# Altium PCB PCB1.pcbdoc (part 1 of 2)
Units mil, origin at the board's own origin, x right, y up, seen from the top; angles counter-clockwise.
Board outline 1377.9 x 2559.1 mil, 4 copper layers (Top Layer, Inner1, Inner2, Bottom Layer), stack 62.5 mil thick; 243 components, 192 nets, 1028 pads, 96 vias.
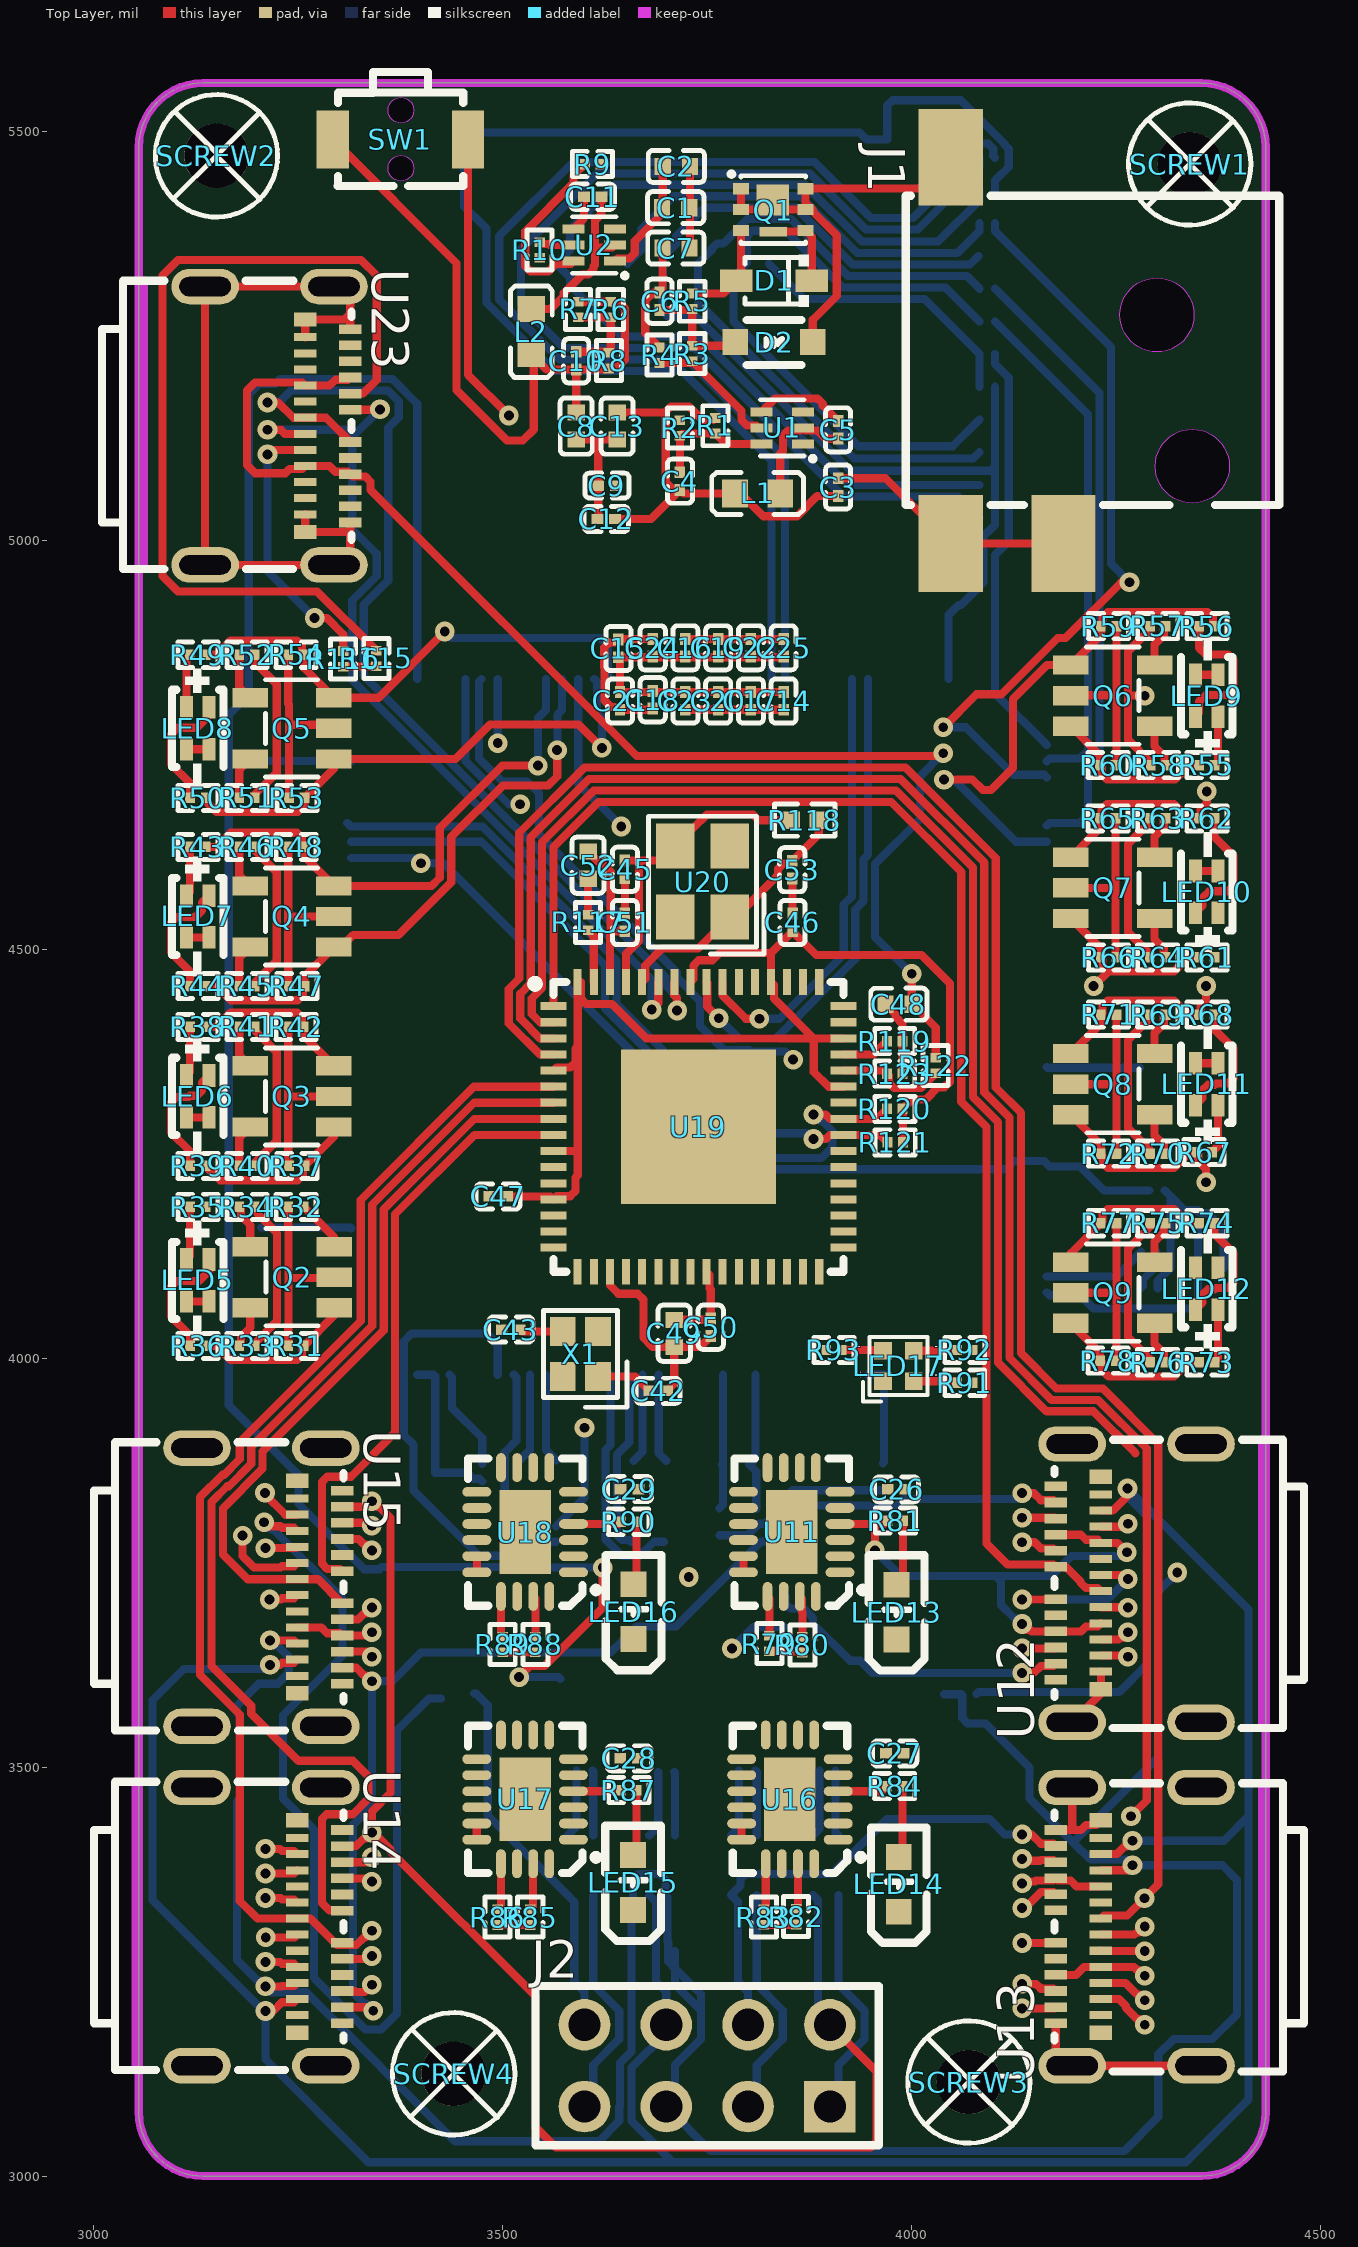
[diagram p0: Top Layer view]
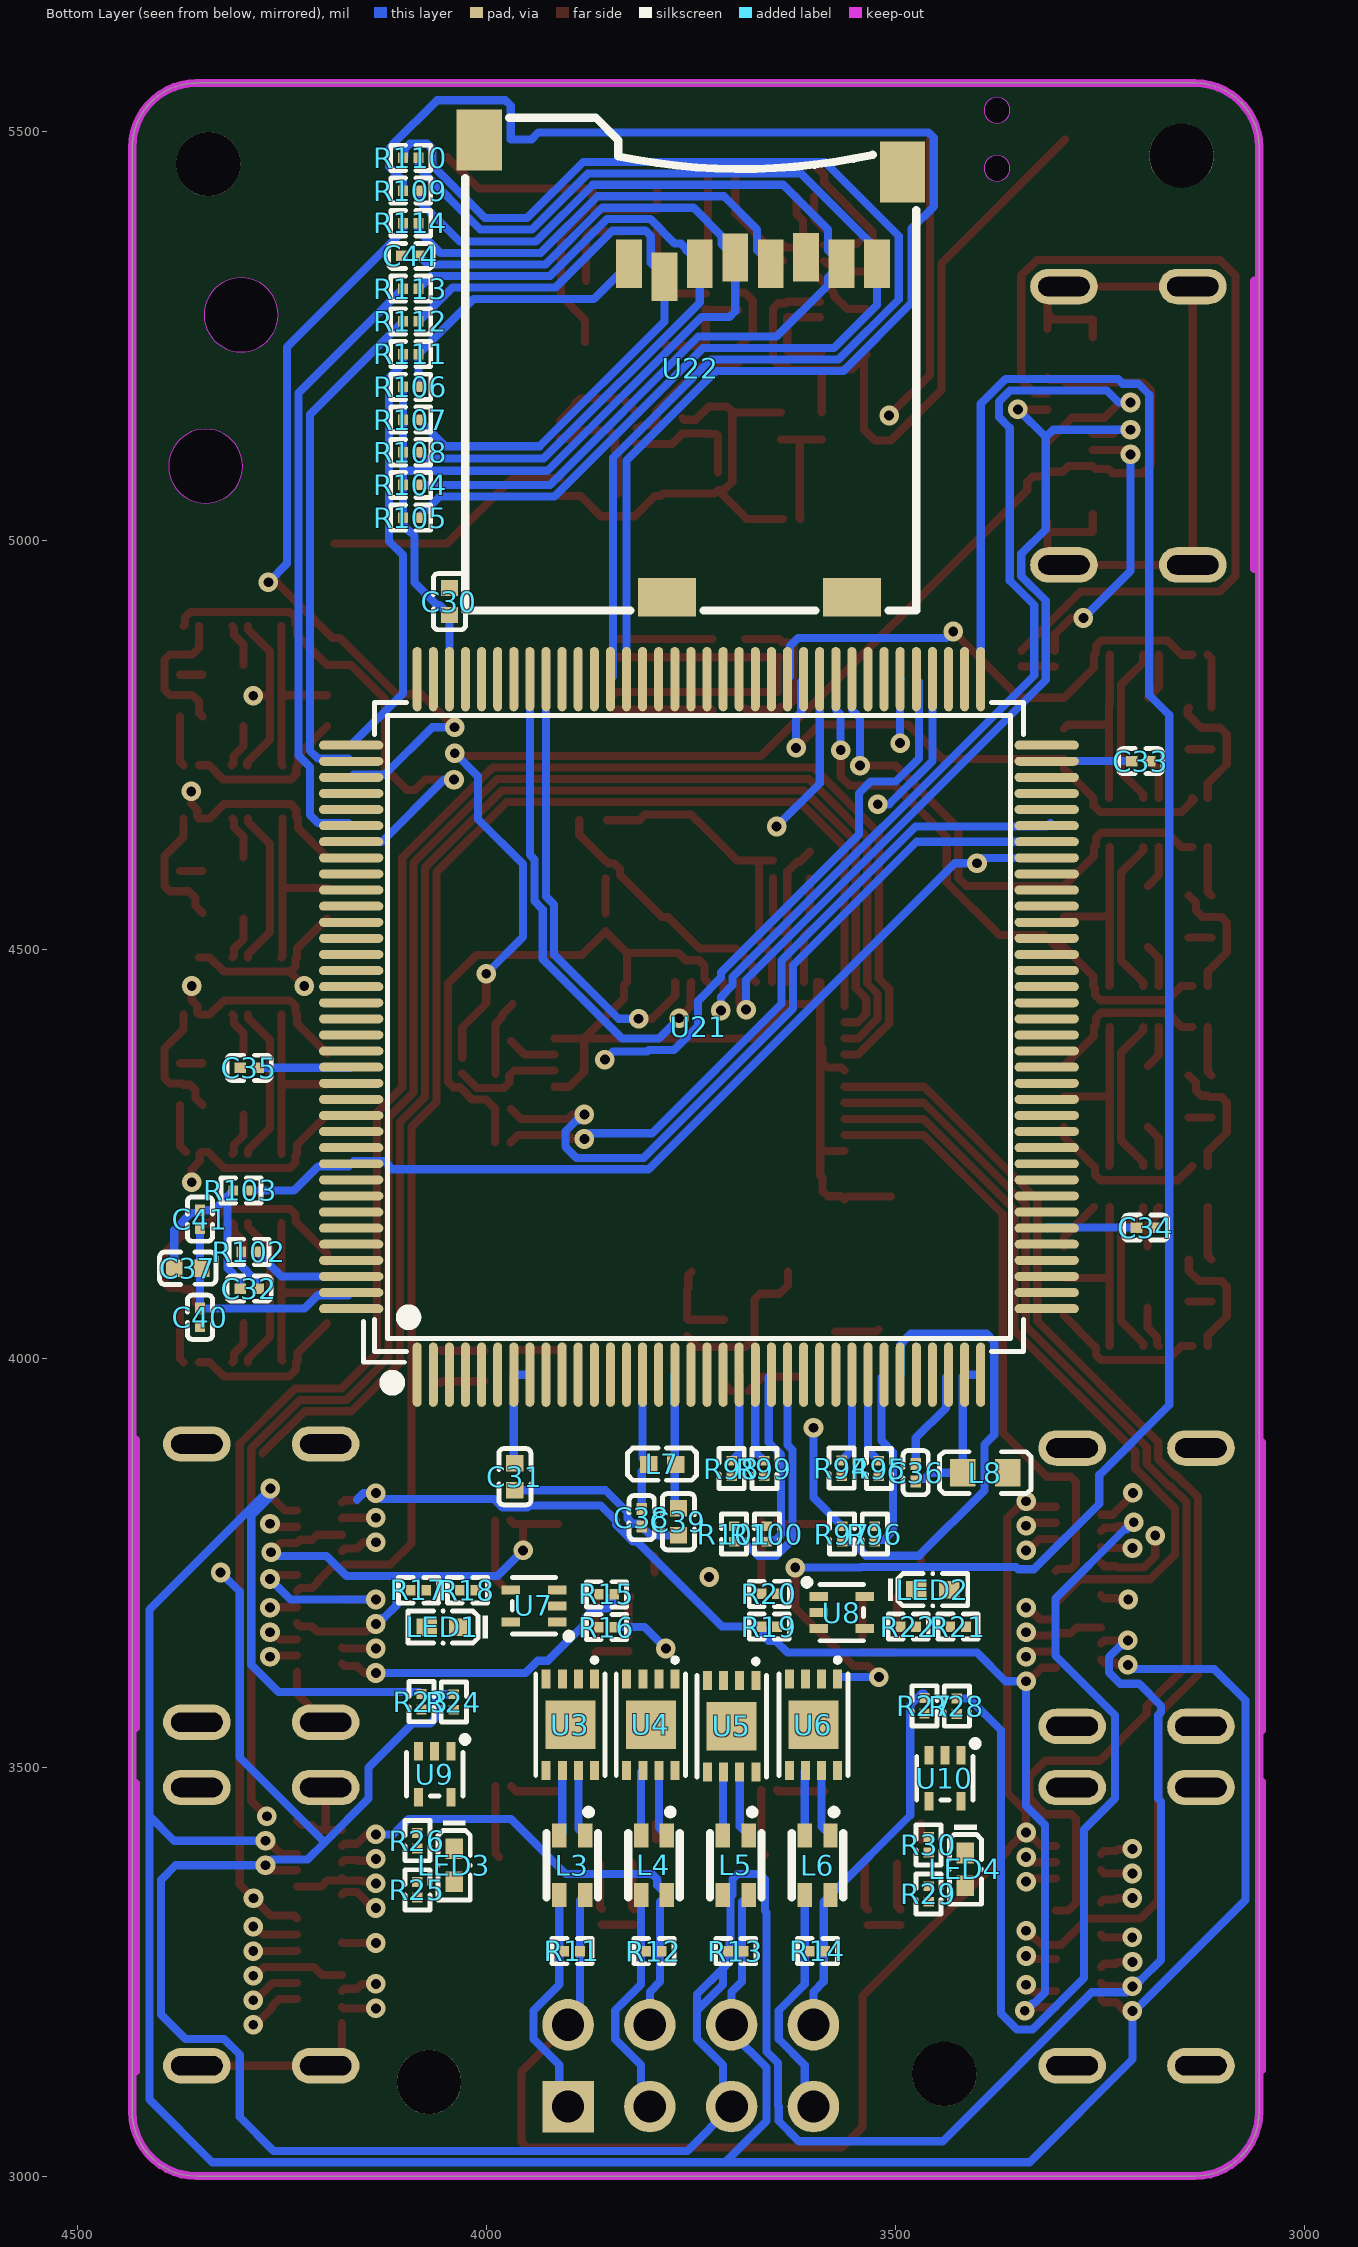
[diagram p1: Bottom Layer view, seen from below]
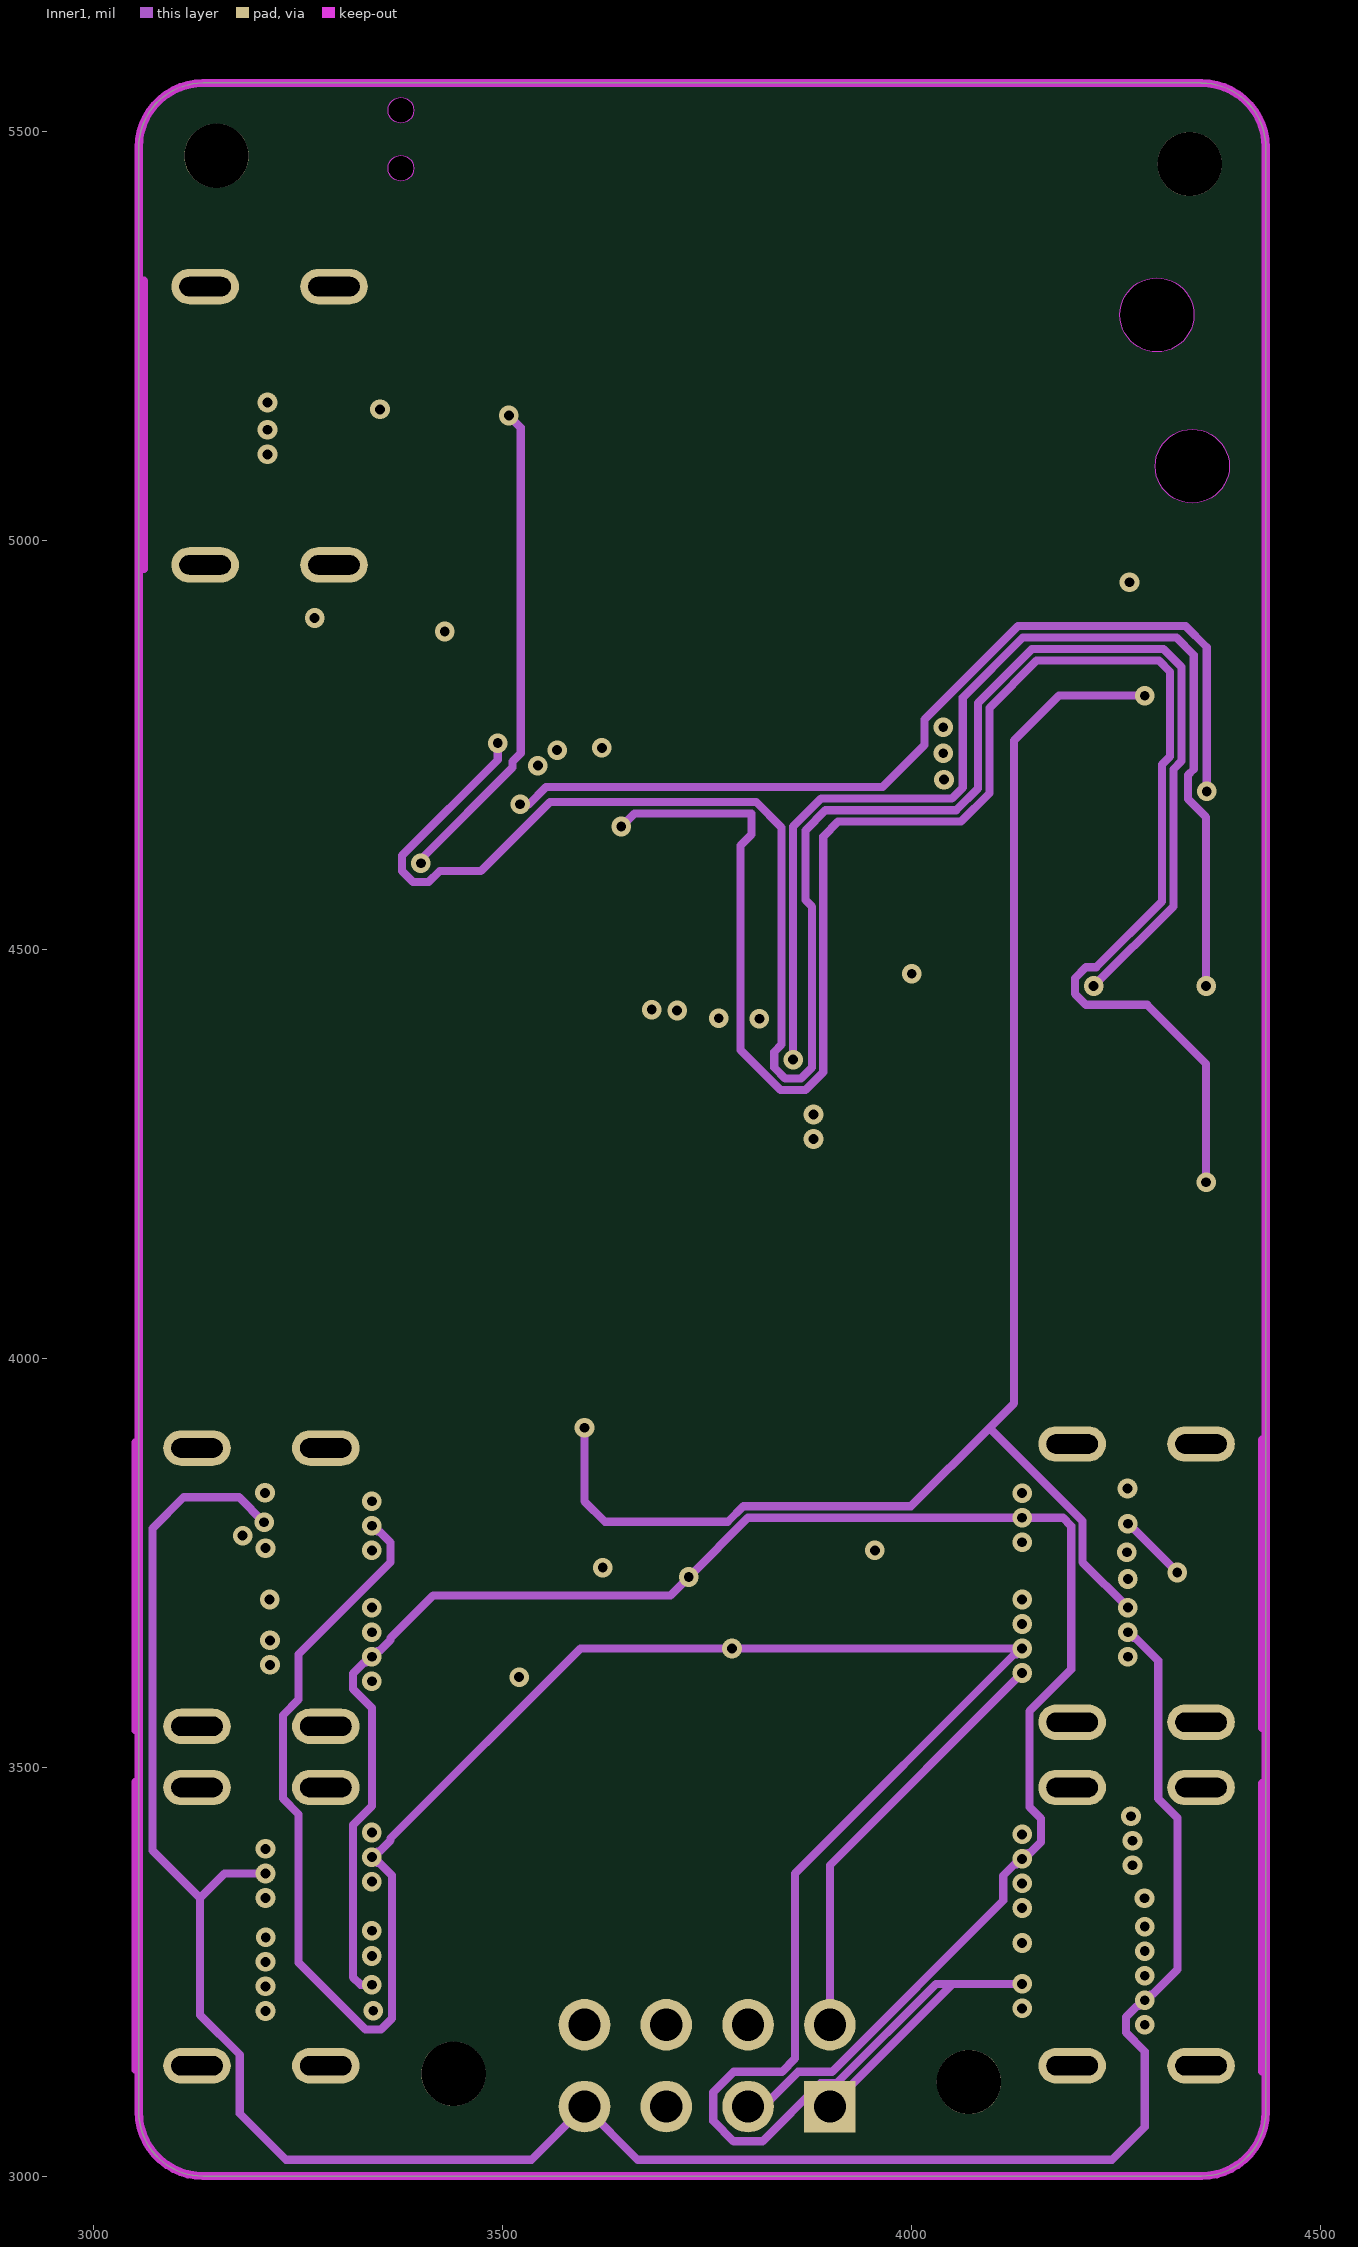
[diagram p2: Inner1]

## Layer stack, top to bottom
Top Layer: signal copper 1.4
Dielectric1: surface 8.3, 7628 RC49% 8.6mil, Dk 0
Inner1: signal copper 0.6
Dielectric2: surface 41.9, 1.1mm H/HOZ Copper, Dk 0
Inner2: signal copper 0.6
Dielectric3: surface 8.3, 7628 RC49% 8.6mil, Dk 0
Bottom Layer: signal copper 1.4

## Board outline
3133.5,5559.1 ccw(c3133.5,5480.3) 3054.8,5480.3 3054.8,3078.7 ccw(c3133.5,3078.7) 3133.5,3000 4354,3000 ccw(c4354,3078.7) 4432.7,3078.7 4432.7,5480.3 ccw(c4354,5480.3) 4354,5559.1 3133.5,5559.1

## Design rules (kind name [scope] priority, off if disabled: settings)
BoardOutlineClearance copperThickness1oz [All] p0: genericclearance=10 ignorepadtopadclearanceinfootprint=FALSE except(0: Arc-SplitContinuation Track-SplitContinuation SMDPad-SplitContinuation THPad-SplitContinuation Via-SplitContinuation Fill-SplitContinuation Poly-SplitContinuation Region-SplitContinuation Text-SplitContinuation)
BoardOutlineClearance copperThickness2oz [All] p0: genericclearance=10 ignorepadtopadclearanceinfootprint=FALSE except(0: Arc-SplitContinuation Track-SplitContinuation SMDPad-SplitContinuation THPad-SplitContinuation Via-SplitContinuation Fill-SplitContinuation Poly-SplitContinuation Region-SplitContinuation Text-SplitContinuation)
BoardOutlineClearance Plane_innerPlane [All] p0: genericclearance=10 ignorepadtopadclearanceinfootprint=FALSE except(0: Arc-SplitContinuation Track-SplitContinuation SMDPad-SplitContinuation THPad-SplitContinuation Via-SplitContinuation Fill-SplitContinuation Poly-SplitContinuation Region-SplitContinuation Text-SplitContinuation)
BoardOutlineClearance Copper_copperRegion [All] p0: genericclearance=10 ignorepadtopadclearanceinfootprint=FALSE except(0: Arc-SplitContinuation Track-SplitContinuation SMDPad-SplitContinuation THPad-SplitContinuation Via-SplitContinuation Fill-SplitContinuation Poly-SplitContinuation Region-SplitContinuation Text-SplitContinuation)
BoardOutlineClearance otherClearance [All] p0: genericclearance=10 ignorepadtopadclearanceinfootprint=FALSE except(0: Arc-SplitContinuation Track-SplitContinuation SMDPad-SplitContinuation THPad-SplitContinuation Via-SplitContinuation Fill-SplitContinuation Poly-SplitContinuation Region-SplitContinuation Text-SplitContinuation)
Clearance copperThickness1oz [All] p1: gap=7 ignorepadtopadclearanceinfootprint=FALSE
Clearance copperThickness2oz [All] p1: gap=7 ignorepadtopadclearanceinfootprint=FALSE
Clearance Plane_innerPlane [All] p1: gap=7 ignorepadtopadclearanceinfootprint=FALSE
Clearance Copper_copperRegion [All] p1: gap=7 ignorepadtopadclearanceinfootprint=FALSE
Clearance otherClearance [All] p1: gap=7 ignorepadtopadclearanceinfootprint=FALSE
DiffPairsRouting differentialPair [All] p1: maxuncoupledlength=10 minlimit=6 maxlimit=Infinity mostfreqgap=6 toplayer_minwidth=5 toplayer_prefwidth=10 toplayer_maxwidth=100 bottomlayer_minwidth=5 bottomlayer_prefwidth=10 bottomlayer_maxwidth=100 midlayer1_minwidth=5 midlayer1_prefwidth=10 midlayer1_maxwidth=100 midlayer2_minwidth=5 midlayer2_prefwidth=10 midlayer2_maxwidth=100
PasteMaskExpansion pasteMaskExpansion [All] p1: expansion=0
PlaneConnect innerPlane [All] p1: planeconnectstyle=Relief reliefexpansion=20 reliefentries=4 reliefconductorwidth=10 reliefairgap=10
PolygonConnect copperRegion [All] p1: connectstyle=Relief reliefentries=4 reliefconductorwidth=10 polygonreliefangle="90 Angle" airgapwidth=10
RoutingVias viaSize [All] p1: viastyle="Through Hole" holewidth=12.0078 minholewidth=11.811 maxholewidth=248.0314 width=12.0078 minwidth=11.811 maxwidth=248.0314
SolderMaskExpansion solderMaskExpansion [IsVia] p1: useseparateexpansions=TRUE expansion=-1000 expansionbottom=-1000
SolderMaskExpansion solderMaskExpansion [All] p2: useseparateexpansions=TRUE expansion=2 expansionbottom=2
Width copperThickness1oz [All] p1: maxlimit=100 minlimit=5 preferedwidth=10
Width copperThickness2oz [All] p1: maxlimit=100 minlimit=8 preferedwidth=10

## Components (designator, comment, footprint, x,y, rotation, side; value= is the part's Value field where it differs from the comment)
C1 "10uF" C0402#1 3711.3,5406.7 r180 top
C2 "10uF" C0402#1 3712.1,5457 r180 top
C3 "100nF" C0201 3909.8,5065 r90 top
C4 "100nF" C0201 3716.5,5072.3 r270 top
C5 "100nF" C0201 3909.8,5135 r270 top
C6 "100nF" C0201 3691.5,5292.3 r270 top
C7 "10uF" C0402#2 3711.5,5357.3 r180 top
C8 "10uF" C0402#3 3589.6,5139.6 r90 top
C9 "100nF" C0201 3627.3,5066.8 r180 top
C10 "100nF" C0201 3589.6,5219.6 r270 top
C11 "100nF" C0201 3609.8,5420 r0 top
C12 "100nF" C0201 3626.5,5026 r180 top
C13 "10uF" C0402#3 3639.6,5139.6 r90 top
C14 "100nF" C0201 3843.2,4803.5 r270 top
C15 "100nF" C0201 3641.3,4867.7 r90 top
C16 "100nF" C0201 3723.2,4868.5 r90 top
C17 "100nF" C0201 3803.2,4803.5 r270 top
C18 "100nF" C0201 3683.2,4805.1 r270 top
C19 "100nF" C0201 3763.2,4868.5 r90 top
C20 "100nF" C0201 3763.2,4803.5 r270 top
C21 "100nF" C0201 3643.2,4803.5 r270 top
C22 "100nF" C0201 3803.2,4868.5 r90 top
C23 "100nF" C0201 3723.2,4803.5 r270 top
C24 "100nF" C0201 3683.2,4868.5 r90 top
C25 "100nF" C0201 3843.2,4868.5 r90 top
C26 "10uF" C0201 3981.3,3839.5 r180 top
C27 "10uF" C0201 3979.1,3516.7 r0 top
C28 "10uF" C0201 3654.3,3510.8 r0 top
C29 "10uF" C0201 3654.8,3840 r0 top
C30 "10uF" C0402#2 4044.8,4925 r270 bottom
C31 "10uF" C0402#2 3964.8,3855 r90 bottom
C32 "100nF" C0201 4289.8,4085 r180 bottom
C33 "100nF" C0201 3199.8,4730 r0 bottom
C34 "100nF" C0201 3193.8,4159.6 r0 bottom
C35 "100nF" C0201 4289.8,4355 r180 bottom
C36 "100nF" C0201 3474.8,3860 r270 bottom
C37 "10uF" C0402#1 4364.8,4110 r180 bottom
C38 "220pF" C0201 3809.8,3805 r270 bottom
C39 "10uF" C0402#2 3764.8,3800 r90 bottom
C40 "100nF" C0201 4349.8,4050 r90 bottom
C41 "100nF" C0201 4349.8,4170 r270 bottom
C42 "12pF" C0201 3689.8,3960 r0 top
C43 "12pF" C0201 3509.8,4035 r0 top
C44 "10uF" C0201 4092.2,5347.6 r180 bottom
C45 "12pF" C0201 3649.2,4597.7 r270 top
C46 "100nF" C0201 3854.2,4532.7 r270 top
C47 "100nF" C0201 3494.2,4197.7 r0 top
C48 "10uF" C0402#3 3984.2,4432.7 r0 top
C49 "10uF" C0402#3 3709.5,4030.4 r90 top
C50 "100nF" C0201 3754.2,4037.7 r90 top
C51 "100nF" C0201 3649.2,4532.7 r270 top
C52 "10uF" C0402#1 3604.2,4602.7 r90 top
C53 "12pF" C0201 3853.8,4597.3 r270 top
D1 "B140WS-7" SOD-323_L1.8-W1.3-LS2.5-RD 3831.5,5317.3 r180 top
D2 "SOD-323" SOD-323_L1.7-W1.3-LS2.5-BI 3831.5,5242.3 r180 top
J1 "DC-044D-2.5A-2.0-SMT" DC-IN-SMD_DC-044D-2.5A-2.0-SMT 4116.5,5232.3 r270 top
J2 "SSQ-104-04-T-D" HDR-TH_8P-P2.54_SSW-104-23-F-D 3749.8,3135 r0 top
L1 "3.3uH" L0603#1 3811.5,5057.3 r180 top
L2 "3.3uH" L0603#1 3534.8,5255 r270 top
L3 "ACM2012-900-2P-T001" FILTER-SMD_4P-L2.0-W1.2-TL_ACM2012E 3894.8,3380 r270 bottom
L4 "ACM2012-900-2P-T001" FILTER-SMD_4P-L2.0-W1.2-TL_ACM2012E 3794.8,3380 r270 bottom
L5 "ACM2012-900-2P-T001" FILTER-SMD_4P-L2.0-W1.2-TL_ACM2012E 3694.8,3380 r270 bottom
L6 "ACM2012-900-2P-T001" FILTER-SMD_4P-L2.0-W1.2-TL_ACM2012E 3594.8,3380 r270 bottom
L7 "2.2uH" L0402 3784.8,3870 r0 bottom
L8 "3.3uH" L0603#2 3389.8,3860 r0 bottom
LED1 "APHHS1005LSECK/J3-PF" LED0402-RD_RED#1 4052.8,3671.2 r0 bottom
LED2 "APHHS1005LSECK/J3-PF" LED0402-RD_RED#2 3453.9,3716.9 r180 bottom
LED3 "APHHS1005LSECK/J3-PF" LED0402-RD_RED#1 4039,3380 r270 bottom
LED4 "APHHS1005LSECK/J3-PF" LED0402-RD_RED#1 3414,3375 r270 bottom
LED5 "HSMF-C163" LED-SMD_L1.6-W0.8_HSMF-C163 3127.1,4095 r270 top
LED6 "HSMF-C163" LED-SMD_L1.6-W0.8_HSMF-C163 3127.1,4320 r270 top
LED7 "HSMF-C163" LED-SMD_L1.6-W0.8_HSMF-C163 3127.1,4540 r270 top
LED8 "HSMF-C163" LED-SMD_L1.6-W0.8_HSMF-C163 3127.1,4770 r270 top
LED9 "HSMF-C163" LED-SMD_L1.6-W0.8_HSMF-C163 4360.6,4810 r90 top
LED10 "HSMF-C163" LED-SMD_L1.6-W0.8_HSMF-C163 4360.6,4570 r90 top
LED11 "HSMF-C163" LED-SMD_L1.6-W0.8_HSMF-C163 4360.6,4335 r90 top
LED12 "HSMF-C163" LED-SMD_L1.6-W0.8_HSMF-C163 4360.6,4085 r90 top
LED13 "SLED-0603-H0_8MM" LED0603-R-RD_RED 3981.3,3689.5 r90 top
LED14 "SLED-0603-H0_8MM" LED0603-R-RD_RED 3984.1,3356.7 r90 top
LED15 "SLED-0603-H0_8MM" LED0603-R-RD_RED 3659.2,3358.9 r90 top
LED16 "SLED-0603-H0_8MM" LED0603-R-RD_RED 3659.8,3690 r90 top
LED17 "TZ1615RGB3U-Common Yang" LED-SMD_TZ1615RGB3U-COMMON-YANG 3983.6,3990.4 r0 top
Q1 "AON2403" DFN-6_L2.0-W2.0-P0.65-BL-EP-1 3830.6,5403.7 r270 top
Q2 "QS5K2TR" SOT-23-5_L2.9-W1.6-P0.95-LS2.8-TL 3242.4,4099 r180 top
Q3 "QS5K2TR" SOT-23-5_L2.9-W1.6-P0.95-LS2.8-TL 3242.1,4320 r180 top
Q4 "QS5K2TR" SOT-23-5_L2.9-W1.6-P0.95-LS2.8-TL 3242.1,4540 r180 top
Q5 "QS5K2TR" SOT-23-5_L2.9-W1.6-P0.95-LS2.8-TL 3242.1,4770 r180 top
Q6 "QS5K2TR" SOT-23-5_L2.9-W1.6-P0.95-LS2.8-TL 4245.6,4810 r0 top
Q7 "QS5K2TR" SOT-23-5_L2.9-W1.6-P0.95-LS2.8-TL 4245.6,4575 r0 top
Q8 "QS5K2TR" SOT-23-5_L2.9-W1.6-P0.95-LS2.8-TL 4245.6,4335 r0 top
Q9 "QS5K2TR" SOT-23-5_L2.9-W1.6-P0.95-LS2.8-TL 4245.6,4080 r0 top
R1 "52.3kΩ" R0201#1 3759.8,5140 r90 top
R2 "10kΩ" R0201#1 3716.5,5137.3 r90 top
R3 "10kΩ" R0201#2 3731.5,5228.2 r90 top
R4 "10kΩ" R0201#1 3691.5,5226.3 r270 top
R5 "1kΩ" R0201#1 3731.5,5292.3 r270 top
R6 "100kΩ" R0201#1 3631.9,5282.2 r90 top
R7 "100kΩ" R0201#1 3591.9,5282.2 r90 top
R8 "100kΩ" R0201#1 3629.6,5219.6 r270 top
R9 "10kΩ" R0201#1 3609.8,5460 r180 top
R10 "10kΩ" R0201#1 3544.8,5355 r270 top
R11 "62Ω" R0201#1 3894.8,3275 r180 bottom
R12 "62Ω" R0201#1 3794.8,3275 r180 bottom
R13 "62Ω" R0201#1 3694.8,3275 r180 bottom
R14 "62Ω" R0201#1 3594.8,3275 r180 bottom
R15 "10kΩ" R0201#1 3852.8,3711.2 r0 bottom
R16 "10kΩ" R0201#1 3852.8,3671.2 r0 bottom
R17 "100kΩ" R0201#1 4082.8,3716.2 r0 bottom
R18 "2.7kΩ" R0201#1 4022.8,3716.2 r0 bottom
R19 "10kΩ" R0201#2 3653.9,3671.9 r180 bottom
R20 "10kΩ" R0201#2 3653.9,3711.9 r180 bottom
R21 "100kΩ" R0201#1 3422.9,3671.9 r180 bottom
R22 "2.7kΩ" R0201#2 3483.9,3671.9 r180 bottom
R23 "10kΩ" R0201#1 4079,3580 r270 bottom
R24 "10kΩ" R0201#1 4039.5,3579.5 r270 bottom
R25 "100kΩ" R0201#1 4084,3350 r270 bottom
R26 "2.7kΩ" R0201#1 4084,3410 r270 bottom
R27 "10kΩ" R0201#1 3464,3575 r270 bottom
R28 "10kΩ" R0201#1 3424.5,3574.5 r270 bottom
R29 "100kΩ" R0201#1 3459,3345 r270 bottom
R30 "2.7kΩ" R0201#1 3459,3405 r270 bottom
R31 "10kΩ" R0201#1 3247.1,4015 r0 top
R32 "10kΩ" R0201#1 3247.1,4185 r0 top
R33 "1kΩ" R0201#1 3187.1,4015 r0 top
R34 "100Ω" R0201#1 3187.1,4185 r0 top
R35 "100Ω" R0201#1 3127.1,4185 r0 top
R36 "100Ω" R0201#1 3127.1,4015 r0 top
R37 "10kΩ" R0201#1 3248.1,4235 r0 top
R38 "100Ω" R0201#1 3127.1,4405 r0 top
R39 "100Ω" R0201#1 3127.1,4235 r0 top
R40 "1kΩ" R0201#1 3187.1,4235 r0 top
R41 "100Ω" R0201#1 3187.1,4405 r0 top
R42 "10kΩ" R0201#1 3247.1,4405 r0 top
R43 "100Ω" R0201#1 3127.1,4625 r0 top
R44 "100Ω" R0201#1 3127.1,4455 r0 top
R45 "1kΩ" R0201#1 3187.1,4455 r0 top
R46 "100Ω" R0201#1 3187.1,4625 r0 top
R47 "10kΩ" R0201#1 3248.1,4455 r0 top
R48 "10kΩ" R0201#1 3247.1,4625 r0 top
R49 "100Ω" R0201#1 3127.1,4860 r0 top
R50 "100Ω" R0201#1 3127.1,4685 r0 top
R51 "1kΩ" R0201#1 3187.1,4685 r0 top
R52 "100Ω" R0201#1 3187.1,4860 r0 top
R53 "10kΩ" R0201#1 3248.1,4685 r0 top
R54 "10kΩ" R0201#1 3247.1,4860 r0 top
R55 "100Ω" R0201#1 4360.6,4725 r180 top
R56 "100Ω" R0201#1 4360.6,4895 r0 top
R57 "1kΩ" R0201#1 4300.6,4895 r180 top
R58 "100Ω" R0201#1 4301.6,4725 r180 top
R59 "10kΩ" R0201#1 4240.6,4895 r180 top
R60 "10kΩ" R0201#1 4239.6,4725 r180 top
R61 "100Ω" R0201#1 4360.6,4490 r180 top
R62 "100Ω" R0201#1 4360.6,4660 r180 top
R63 "1kΩ" R0201#1 4300.6,4660 r180 top
R64 "100Ω" R0201#1 4300.6,4490 r180 top
R65 "10kΩ" R0201#1 4239.6,4660 r180 top
R66 "10kΩ" R0201#1 4240.6,4490 r180 top
R67 "100Ω" R0201#1 4357.5,4252 r180 top
R68 "100Ω" R0201#1 4360.6,4420 r180 top
R69 "1kΩ" R0201#1 4300.6,4420 r180 top
R70 "100Ω" R0201#1 4300.6,4250 r180 top
R71 "10kΩ" R0201#1 4240.6,4420 r180 top
R72 "10kΩ" R0201#1 4240.6,4250 r180 top
R73 "100Ω" R0201#1 4360.6,3995 r180 top
R74 "100Ω" R0201#1 4360.6,4165 r180 top
R75 "1kΩ" R0201#1 4300.6,4165 r180 top
R76 "100Ω" R0201#1 4300.6,3995 r180 top
R77 "10kΩ" R0201#1 4240.6,4165 r180 top
R78 "10kΩ" R0201#1 4239.7,3997 r180 top
R79 "28kΩ" R0201#1 3825.8,3651.1 r270 top
R80 "33kΩ" R0201#1 3866.3,3649.5 r270 top
R81 "3.3kΩ" R0201#1 3979.8,3801.4 r180 top
R82 "33kΩ" R0201#2 3858.6,3317.3 r270 top
R83 "28kΩ" R0201#1 3819.1,3316.7 r270 top
R84 "3.3kΩ" R0201#1 3979.1,3476.7 r180 top
R85 "33kΩ" R0201#2 3533.5,3316.6 r270 top
R86 "28kΩ" R0201#2 3493.5,3316.6 r270 top
R87 "3.3kΩ" R0201#1 3654,3472 r180 top
R88 "33kΩ" R0201#1 3539.8,3650 r270 top
R89 "28kΩ" R0201#1 3499.8,3650 r270 top
R90 "3.3kΩ" R0201#1 3653.8,3800 r180 top
R91 "1kΩ" R0201#1 4064.8,3970 r180 top
R92 "1kΩ" R0201#1 4064.8,4010 r0 top
R93 "1kΩ" R0201#1 3904.8,4010 r180 top
R94 "100kΩ" R0201#1 3565.3,3865.5 r270 bottom
R95 "100kΩ" R0201#1 3519.8,3865 r270 bottom
R96 "100kΩ" R0201#1 3524.8,3785 r90 bottom
R97 "100kΩ" R0201#1 3564.8,3785 r90 bottom
R98 "100kΩ" R0201#1 3699.8,3865 r270 bottom
R99 "100kΩ" R0201#1 3659.8,3865 r270 bottom
R100 "100kΩ" R0201#1 3656.8,3785 r90 bottom
R101 "100kΩ" R0201#1 3696.8,3785 r90 bottom
R102 "10kΩ" R0201#1 4289.8,4130 r0 bottom
R103 "10kΩ" R0201#1 4299.8,4205 r180 bottom
R104 "10kΩ" R0201#3 4092.2,5067.6 r0 bottom
R105 "10kΩ" R0201#3 4092.2,5027.6 r0 bottom
R106 "10kΩ" R0201#3 4092.2,5187.6 r0 bottom
R107 "10kΩ" R0201#3 4092.2,5147.6 r0 bottom
R108 "10kΩ" R0201#3 4092.2,5107.6 r0 bottom
R109 "0Ω" R0201#3 4092.2,5427.6 r0 bottom
R110 "0Ω" R0201#3 4092.2,5467.6 r0 bottom
R111 "0Ω" R0201#3 4092.2,5227.6 r0 bottom
R112 "0Ω" R0201#3 4092.2,5267.6 r0 bottom
R113 "0Ω" R0201#3 4092.2,5307.6 r0 bottom
R114 "0Ω" R0201#3 4092.2,5387.6 r0 bottom
R115 "10kΩ" R0201#1 3345.3,4855.5 r270 top
R116 "10kΩ" R0201#1 3304.8,4855 r90 top
R117 "12kΩ" R0201#1 3604.2,4532.7 r90 top
R118 "1MΩ" R0402 3869.2,4657.7 r180 top
R119 "10kΩ" R0201#1 3979.2,4387.7 r180 top
R120 "10kΩ" R0201#1 3979.2,4304.8 r180 top
R121 "10kΩ" R0201#1 3979.7,4263.9 r180 top
R122 "100kΩ" R0201#1 4029.2,4357.7 r270 top
R123 "100kΩ" R0201#1 3979.2,4347.7 r0 top
SCREW1 "" Screw-Hole-M2 4339.8,5460 r0 top
SCREW2 "" Screw-Hole-M2 3149.8,5470 r0 top
SCREW3 "" Screw-Hole-M2 4069.8,3115 r0 top
SCREW4 "" Screw-Hole-M2 3439.8,3125 r0 top
SW1 "TS-1809-T20" SW-SMD_L3.9-W2.9-LS4.8SWQC_SPST 3374.8,5490 r90 top
U1 "AP62300Z6-7" SOT-563-6_L1.6-W1.2-P0.50-LS1.6-BL#1 3841.5,5137.3 r90 top
U2 "AP62300Z6-7" SOT-563-6_L1.6-W1.2-P0.50-LS1.6-BL#2 3611.7,5361 r90 top
U3 "MCP2542FDT-E/MNY" TDFN-8_L3.0-W2.0-P0.50-TL-EP#1 3897,3551.8 r270 bottom
U4 "MCP2542FDT-E/MNY" TDFN-8_L3.0-W2.0-P0.50-TL-EP#2 3798.5,3551.8 r270 bottom
U5 "MCP2542FDT-E/MNY" TDFN-8_L3.0-W2.0-P0.50-TL-EP#1 3699.8,3550 r270 bottom
U6 "MCP2542FDT-E/MNY" TDFN-8_L3.0-W2.0-P0.50-TL-EP#1 3599.8,3551.8 r270 bottom
U7 "NCS20071XV53T2G" SOT-553-5_L1.6-W1.2-P0.50-LS1.6-BL#1 3941.4,3697.1 r90 bottom
U8 "NCS20071XV53T2G" SOT-553-5_L1.6-W1.2-P0.50-LS1.6-BL#2 3565.2,3689 r270 bottom
U9 "NCS20071XV53T2G" SOT-553-5_L1.6-W1.2-P0.50-LS1.6-BL#3 4062.8,3491.4 r0 bottom
U10 "NCS20071XV53T2G" SOT-553-5_L1.6-W1.2-P0.50-LS1.6-BL#1 3439,3486.4 r0 bottom
U11 "TPS25944ARVCR" WQFN-20_L4.0-W3.0-P0.50-BL-EP#1 3853.1,3787.4 r90 top
U12 "USB4081-03-A" USB-SMD_USB4081-03-A#1 4264.8,3725 r90 top
U13 "USB4081-03-A" USB-SMD_USB4081-03-A#1 4264.8,3305 r90 top
U14 "USB4081-03-A" USB-SMD_USB4081-03-A#2 3214.8,3305 r270 top
U15 "USB4081-03-A" USB-SMD_USB4081-03-A#2 3214.8,3720 r270 top
U16 "TPS25944ARVCR" WQFN-20_L4.0-W3.0-P0.50-BL-EP#2 3851,3460.6 r90 top
U17 "TPS25944ARVCR" WQFN-20_L4.0-W3.0-P0.50-BL-EP#3 3527.2,3460.6 r90 top
U18 "TPS25944ARVCR" WQFN-20_L4.0-W3.0-P0.50-BL-EP#4 3527.2,3787.4 r90 top
U19 "USB2517-JZX-TR" QFN-64_L9.0-W9.0-P0.50-BL-EP4.8 3739.2,4282.7 r270 top
U20 "24MHz" CRYSTAL-SMD_4P-L3.2-W2.5-BL 3744.2,4582.7 r90 top
U21 "STM32H725ZGT6" LQFP-144_L20.0-W20.0-P0.50-LS22.0-BL 3739.8,4405 r180 bottom
U22 "XDTP-1001-098" MICRO-SD-SMD_XDTP-1001-098 3749.8,5210 r0 bottom
U23 "USB4081-03-A" USB-SMD_USB4081-03-A#3 3224.8,5140 r270 top
X1 "25MHz" CRYSTAL-SMD_4P-L2.0-W1.6-BL 3594.8,4005 r90 top

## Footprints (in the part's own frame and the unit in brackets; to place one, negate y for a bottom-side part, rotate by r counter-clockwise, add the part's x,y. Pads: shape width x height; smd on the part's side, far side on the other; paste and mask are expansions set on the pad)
C0201 [mil]
  rect 14.5x12.8 smd paste-3937 mask+2: 1(-10.8,0) 2(10.8,0)
  silkscreen extent -27,-15 27,15
C0402#1 [mil]
  rect 19.7x21.3 smd: 1(-16.5,0) 2(16.6,0)
  silkscreen extent -34,-20 34,20
C0402#2 [mil]
  rect 19.7x21.3 smd: 1(-16.5,0) 2(16.5,0)
  silkscreen extent -34,-20 34,20
C0402#3 [mil]
  rect 19.7x21.3 smd: 1(-16.6,0) 2(16.5,0)
  silkscreen extent -34,-20 34,20
CRYSTAL-SMD_4P-L2.0-W1.6-BL [mil]
  rect 35.4x31.5 smd: 1(-27.6,-21.6) 2(27.6,-21.6) 3(27.6,21.7) 4(-27.6,21.7)
  silkscreen extent -65,-57 53,45
CRYSTAL-SMD_4P-L3.2-W2.5-BL [mil]
  rect 55.1x47.2 smd: 1(-43.3,-33.4) 2(43.3,-33.4) 3(43.3,33.5) 4(-43.3,33.5)
  silkscreen extent -89,-75 80,66
DC-IN-SMD_DC-044D-2.5A-2.0-SMT [mil]
  rect 118.1x78.7 smd: 3(-236.2,-68.9) 4(236.3,-68.9) 5(236.3,68.9)
  Board Outline Layer lines w0.1: -43.3,137.8 -37.4,138.2 -31.6,139.3 -25.9,141.2 -20.6,143.9 -15.7,147.2 -11.3,151.1 -7.4,155.5 -4.1,160.4 -1.4,165.7 0.5,171.4 1.6,177.2 2,183.1 1.6,189 0.5,194.8 -1.4,200.4 -4.1,205.7 -7.4,210.6 -11.3,215.1 -15.7,219 -20.6,222.3 -25.9,224.9 -31.6,226.8 -37.4,228 -43.3,228.3 -49.2,228 -55,226.8 -60.6,224.9 -65.9,222.3 -70.8,219 -75.3,215.1 -79.2,210.6 -82.5,205.7 -85.1,200.4 -87,194.8 -88.2,189 -88.6,183.1 -88.2,177.2 -87,171.4 -85.1,165.7 -82.5,160.4 -79.2,155.5 -75.3,151.1 -70.8,147.2 -65.9,143.9 -60.6,141.2 -55,139.3 -49.2,138.2 -43.3,137.8 ; 141.8,181.1 147.7,181.5 153.5,182.6 159.1,184.6 164.4,187.2 169.3,190.5 173.8,194.4 177.7,198.8 181,203.7 183.6,209.1 185.5,214.7 186.7,220.5 187,226.4 186.7,232.3 185.5,238.1 183.6,243.7 181,249 177.7,253.9 173.8,258.4 169.3,262.3 164.4,265.6 159.1,268.2 153.5,270.1 147.7,271.3 141.8,271.7 135.9,271.3 130,270.1 124.4,268.2 119.1,265.6 114.2,262.3 109.8,258.4 105.8,253.9 102.6,249 99.9,243.7 98,238.1 96.9,232.3 96.5,226.4 96.9,220.5 98,214.7 99.9,209.1 102.6,203.7 105.8,198.8 109.8,194.4 114.2,190.5 119.1,187.2 124.4,184.6 130,182.6 135.9,181.5 141.8,181.1
  Board Outline Layer region: 187,226.4 186.7,220.5 185.5,214.7 183.6,209.1 181,203.7 177.7,198.8 173.8,194.4 169.3,190.5 164.4,187.2 159.1,184.6 153.5,182.6 147.7,181.5 141.8,181.1 135.9,181.5 130,182.6 124.4,184.6 119.1,187.2 114.2,190.5 109.8,194.4 105.8,198.8 102.6,203.7 99.9,209.1 98,214.7 96.9,220.5 96.5,226.4 96.9,232.3 98,238.1 99.9,243.7 102.6,249 105.8,253.9 109.8,258.4 114.2,262.3 119.1,265.6 124.4,268.2 130,270.1 135.9,271.3 141.8,271.7 147.7,271.3 153.5,270.1 159.1,268.2 164.4,265.6 169.3,262.3 173.8,258.4 177.7,253.9 181,249 183.6,243.7 185.5,238.1 186.7,232.3
  Board Outline Layer region: 187,226.4 186.7,220.5 185.5,214.7 183.6,209.1 181,203.7 177.7,198.8 173.8,194.4 169.3,190.5 164.4,187.2 159.1,184.6 153.5,182.6 147.7,181.5 141.8,181.1 135.9,181.5 130,182.6 124.4,184.6 119.1,187.2 114.2,190.5 109.8,194.4 105.8,198.8 102.6,203.7 99.9,209.1 98,214.7 96.9,220.5 96.5,226.4 96.9,232.3 98,238.1 99.9,243.7 102.6,249 105.8,253.9 109.8,258.4 114.2,262.3 119.1,265.6 124.4,268.2 130,270.1 135.9,271.3 141.8,271.7 147.7,271.3 153.5,270.1 159.1,268.2 164.4,265.6 169.3,262.3 173.8,258.4 177.7,253.9 181,249 183.6,243.7 185.5,238.1 186.7,232.3
  Board Outline Layer region: 2,183.1 1.6,177.2 0.5,171.4 -1.4,165.7 -4.1,160.4 -7.4,155.5 -11.3,151.1 -15.7,147.2 -20.6,143.9 -25.9,141.2 -31.6,139.3 -37.4,138.2 -43.3,137.8 -49.2,138.2 -55,139.3 -60.6,141.2 -65.9,143.9 -70.8,147.2 -75.3,151.1 -79.2,155.5 -82.5,160.4 -85.1,165.7 -87,171.4 -88.2,177.2 -88.6,183.1 -88.2,189 -87,194.8 -85.1,200.4 -82.5,205.7 -79.2,210.6 -75.3,215.1 -70.8,219 -65.9,222.3 -60.6,224.9 -55,226.8 -49.2,228 -43.3,228.3 -37.4,228 -31.6,226.8 -25.9,224.9 -20.6,222.3 -15.7,219 -11.3,215.1 -7.4,210.6 -4.1,205.7 -1.4,200.4 0.5,194.8 1.6,189
  Board Outline Layer region: 2,183.1 1.6,177.2 0.5,171.4 -1.4,165.7 -4.1,160.4 -7.4,155.5 -11.3,151.1 -15.7,147.2 -20.6,143.9 -25.9,141.2 -31.6,139.3 -37.4,138.2 -43.3,137.8 -49.2,138.2 -55,139.3 -60.6,141.2 -65.9,143.9 -70.8,147.2 -75.3,151.1 -79.2,155.5 -82.5,160.4 -85.1,165.7 -87,171.4 -88.2,177.2 -88.6,183.1 -88.2,189 -87,194.8 -85.1,200.4 -82.5,205.7 -79.2,210.6 -75.3,215.1 -70.8,219 -65.9,222.3 -60.6,224.9 -55,226.8 -49.2,228 -43.3,228.3 -37.4,228 -31.6,226.8 -25.9,224.9 -20.6,222.3 -15.7,219 -11.3,215.1 -7.4,210.6 -4.1,205.7 -1.4,200.4 0.5,194.8 1.6,189
  Multi-Layer board cut-out: 187,226.4 186.7,220.5 185.5,214.7 183.6,209.1 181,203.7 177.7,198.8 173.8,194.4 169.3,190.5 164.4,187.2 159.1,184.6 153.5,182.6 147.7,181.5 141.8,181.1 135.9,181.5 130,182.6 124.4,184.6 119.1,187.2 114.2,190.5 109.8,194.4 105.8,198.8 102.6,203.7 99.9,209.1 98,214.7 96.9,220.5 96.5,226.4 96.9,232.3 98,238.1 99.9,243.7 102.6,249 105.8,253.9 109.8,258.4 114.2,262.3 119.1,265.6 124.4,268.2 130,270.1 135.9,271.3 141.8,271.7 147.7,271.3 153.5,270.1 159.1,268.2 164.4,265.6 169.3,262.3 173.8,258.4 177.7,253.9 181,249 183.6,243.7 185.5,238.1 186.7,232.3
  Multi-Layer board cut-out: 2,183.1 1.6,177.2 0.5,171.4 -1.4,165.7 -4.1,160.4 -7.4,155.5 -11.3,151.1 -15.7,147.2 -20.6,143.9 -25.9,141.2 -31.6,139.3 -37.4,138.2 -43.3,137.8 -49.2,138.2 -55,139.3 -60.6,141.2 -65.9,143.9 -70.8,147.2 -75.3,151.1 -79.2,155.5 -82.5,160.4 -85.1,165.7 -87,171.4 -88.2,177.2 -88.6,183.1 -88.2,189 -87,194.8 -85.1,200.4 -82.5,205.7 -79.2,210.6 -75.3,215.1 -70.8,219 -65.9,222.3 -60.6,224.9 -55,226.8 -49.2,228 -43.3,228.3 -37.4,228 -31.6,226.8 -25.9,224.9 -20.6,222.3 -15.7,219 -11.3,215.1 -7.4,210.6 -4.1,205.7 -1.4,200.4 0.5,194.8 1.6,189
  silkscreen extent -189,-124 189,333
DFN-6_L2.0-W2.0-P0.65-BL-EP-1 [mil]
  rect 13.8x19.7 smd: 1(-26.2,-39.4) 2(-0.6,-39.4) 3(24.9,-39.4) 4(24.9,39.4) 5(-0.6,39.4) 6(-26.2,39.4)
  rect 37.4x39.4 smd: 7(-12.3,-0.7)
  rect 11.8x33.5 smd: 8(26.3,0)
  silkscreen extent -47,-54 41,39
FILTER-SMD_4P-L2.0-W1.2-TL_ACM2012E [mil]
  rect 29.5x17.6 smd: 1(-36.4,15.8) 2(-36.4,-15.7) 3(36.4,-15.7) 4(36.4,15.8)
  silkscreen extent -69,-32 39,32
HDR-TH_8P-P2.54_SSW-104-23-F-D [mil]
  rect 63x63 hole 39.4 paste+0 mask+2: 1(150,-50)
  round 63 hole 39.4 paste+0 mask+2: 2(150,50) 3(50,-50) 4(50,50) 5(-50,-50) 6(-50,50) 7(-150,-50) 8(-150,50)
  silkscreen extent -210,-97 210,97
L0402 [mil]
  rect 21.3x21.3 smd: 1(-16.6,0) 2(16.5,0)
  silkscreen extent -42,-20 42,19
L0603#1 [mil]
  rect 31.5x34 smd paste-3937 mask+2: 1(-27.6,0) 2(27.6,0)
  silkscreen extent -56,-26 56,26
L0603#2 [mil]
  rect 31.5x34 smd paste-3937 mask+2: 1(-27.6,0) 2(27.5,0)
  silkscreen extent -56,-26 56,26
LED0402-RD_RED#1 [mil]
  rect 25.1x21.3 smd paste-3937 mask+2: 1(-20,0) 2(20,0)
  silkscreen extent -55,-21 43,21
LED0402-RD_RED#2 [mil]
  rect 25.1x21.3 smd paste-3937 mask+2: 1(-20,0) 2(20.1,0)
  silkscreen extent -55,-21 43,21
LED0603-R-RD_RED [mil]
  rect 31.5x31.5 smd: 1(33.5,0) 2(-33.5,0)
  silkscreen extent -72,-34 70,34
LED-SMD_L1.6-W0.8_HSMF-C163 [mil]
  rect 27.6x15.7 smd: 1(-25.6,13.8) 2(-25.6,-13.8) 3(25.6,13.8) 4(25.6,-13.8)
  silkscreen extent -73,-32 73,32
LED-SMD_TZ1615RGB3U-COMMON-YANG [mm]
  rect 0.551x0.551 smd: 1(-0.475,-0.475) 2(0.475,-0.475) 3(0.475,0.475) 4(-0.475,0.475)
  silkscreen extent -1.1,-1.1 0.9,0.9
LQFP-144_L20.0-W20.0-P0.50-LS22.0-BL [mil]
  oval 11x78.7 smd: 1(-344.5,-425.2) 2(-324.8,-425.2) 3(-305.1,-425.2) 4(-285.4,-425.2) 5(-265.7,-425.2) 6(-246,-425.2) 7(-226.3,-425.2) 8(-206.7,-425.2) 9(-187,-425.2) 10(-167.3,-425.2) 11(-147.6,-425.2) 12(-127.9,-425.2) 13(-108.2,-425.2) 14(-88.5,-425.2) 15(-68.9,-425.2) 16(-49.2,-425.2) 17(-29.5,-425.2) 18(-9.8,-425.2) 19(9.9,-425.2) 20(29.6,-425.2) 21(49.2,-425.2) 22(68.9,-425.2) 23(88.6,-425.2) 24(108.3,-425.2) 25(128,-425.2) 26(147.7,-425.2) 27(167.4,-425.2) 28(187,-425.2) 29(206.7,-425.2) 30(226.4,-425.2) 31(246.1,-425.2) 32(265.8,-425.2) 33(285.5,-425.2) 34(305.2,-425.2) 35(324.8,-425.2) 36(344.5,-425.2) 73(344.5,425.2) 74(324.8,425.2) 75(305.2,425.2) 76(285.5,425.2) 77(265.8,425.2) 78(246.1,425.2) 79(226.4,425.2) 80(206.7,425.2) 81(187,425.2) 82(167.4,425.2) 83(147.7,425.2) 84(128,425.2) 85(108.3,425.2) 86(88.6,425.2) 87(68.9,425.2) 88(49.2,425.2) 89(29.6,425.2) 90(9.9,425.2) 91(-9.8,425.2) 92(-29.5,425.2) 93(-49.2,425.2) 94(-68.9,425.2) 95(-88.5,425.2) 96(-108.2,425.2) 97(-127.9,425.2) 98(-147.6,425.2) 99(-167.3,425.2) 100(-187,425.2) 101(-206.7,425.2) 102(-226.3,425.2) 103(-246,425.2) 104(-265.7,425.2) 105(-285.4,425.2) 106(-305.1,425.2) 107(-324.8,425.2) 108(-344.5,425.2)
  oval 78.7x11 smd: 37(425.2,-344.5) 38(425.2,-324.8) 39(425.2,-305.1) 40(425.2,-285.4) 41(425.2,-265.7) 42(425.2,-246.1) 43(425.2,-226.4) 44(425.2,-206.7) 45(425.2,-187) 46(425.2,-167.3) 47(425.2,-147.6) 48(425.2,-127.9) 49(425.2,-108.3) 50(425.2,-88.6) 51(425.2,-68.9) 52(425.2,-49.2) 53(425.2,-29.5) 54(425.2,-9.8) 55(425.2,9.8) 56(425.2,29.5) 57(425.2,49.2) 58(425.2,68.9) 59(425.2,88.6) 60(425.2,108.3) 61(425.2,127.9) 62(425.2,147.6) 63(425.2,167.3) 64(425.2,187) 65(425.2,206.7) 66(425.2,226.4) 67(425.2,246.1) 68(425.2,265.8) 69(425.2,285.4) 70(425.2,305.1) 71(425.2,324.8) 72(425.2,344.5) 109(-425.2,344.5) 110(-425.2,324.8) 111(-425.2,305.1) 112(-425.2,285.4) 113(-425.2,265.8) 114(-425.2,246.1) 115(-425.2,226.4) 116(-425.2,206.7) 117(-425.2,187) 118(-425.2,167.3) 119(-425.2,147.6) 120(-425.2,127.9) 121(-425.2,108.3) 122(-425.2,88.6) 123(-425.2,68.9) 124(-425.2,49.2) 125(-425.2,29.5) 126(-425.2,9.8) 127(-425.2,-9.8) 128(-425.2,-29.5) 129(-425.2,-49.2) 130(-425.2,-68.9) 131(-425.2,-88.6) 132(-425.2,-108.3) 133(-425.2,-127.9) 134(-425.2,-147.6) 135(-425.2,-167.3) 136(-425.2,-187) 137(-425.2,-206.7) 138(-425.2,-226.4) 139(-425.2,-246.1) 140(-425.2,-265.7) 141(-425.2,-285.4) 142(-425.2,-305.1) 143(-425.2,-324.8) 144(-425.2,-344.5)
  silkscreen extent -410,-443 397,397
MICRO-SD-SMD_XDTP-1001-098 [mil]
  rect 31.5x59.1 smd: 1(75.5,-128) 2(32.2,-112.2) 3(-11.1,-128) 4(-54.4,-135.8) 5(-97.7,-128) 6(-141,-135.9) 7(-184.3,-128) 8(-227.6,-128)
  rect 55.1x74.8 smd: 10(-258.7,-240.2) 10(258.6,-279.5)
  rect 70.9x47.2 smd: 10(-197.3,279.5) 10(29.1,279.5)
  silkscreen extent -276,-307 276,296
QFN-64_L9.0-W9.0-P0.50-BL-EP4.8 [mil]
  rect 9.8x31.5 smd: 1(-147.7,-177.2) 2(-128,-177.2) 3(-108.3,-177.2) 4(-88.6,-177.2) 5(-68.9,-177.2) 6(-49.2,-177.2) 7(-29.6,-177.2) 8(-9.9,-177.2) 9(9.8,-177.2) 10(29.5,-177.2) 11(49.2,-177.2) 12(68.9,-177.2) 13(88.5,-177.2) 14(108.2,-177.2) 15(127.9,-177.2) 16(147.6,-177.2) 33(147.6,177.1) 34(127.9,177.1) 35(108.2,177.1) 36(88.5,177.1) 37(68.9,177.1) 38(49.2,177.1) 39(29.5,177.1) 40(9.8,177.1) 41(-9.9,177.1) 42(-29.6,177.1) 43(-49.2,177.1) 44(-68.9,177.1) 45(-88.6,177.1) 46(-108.3,177.1) 47(-128,177.1) 48(-147.7,177.1)
  rect 31.5x9.8 smd: 17(177.1,-147.7) 18(177.1,-128) 19(177.1,-108.3) 20(177.1,-88.6) 21(177.1,-68.9) 22(177.1,-49.2) 23(177.1,-29.6) 24(177.1,-9.9) 25(177.1,9.8) 26(177.1,29.5) 27(177.1,49.2) 28(177.1,68.9) 29(177.1,88.6) 30(177.1,108.2) 31(177.1,127.9) 32(177.1,147.6) 49(-177.2,147.6) 50(-177.2,127.9) 51(-177.2,108.2) 52(-177.2,88.6) 53(-177.2,68.9) 54(-177.2,49.2) 55(-177.2,29.5) 56(-177.2,9.8) 57(-177.2,-9.9) 58(-177.2,-29.6) 59(-177.2,-49.2) 60(-177.2,-68.9) 61(-177.2,-88.6) 62(-177.2,-108.3) 63(-177.2,-128) 64(-177.2,-147.7)
  rect 189x189 smd: 65(0,0)
  silkscreen extent -180,-205 177,177
R0201#1 [mil]
  rect 11.9x12.8 smd paste-3937 mask+2: 1(-9.5,0) 2(9.5,0)
  silkscreen extent -24,-15 24,15
R0201#2 [mil]
  rect 11.9x12.8 smd paste-3937 mask+2: 1(-9.5,0) 2(9.6,0)
  silkscreen extent -24,-15 24,15
R0201#3 [mil]
  rect 11.9x12.8 smd paste-3937 mask+2: 1(-9.6,0) 2(9.5,0)
  silkscreen extent -24,-15 24,15
R0402 [mil]
  rect 22.3x21.3 smd paste-3937 mask+2: 1(-17,0) 2(17.1,0)
  silkscreen extent -37,-20 37,20
Screw-Hole-M2 [mil]
  round 78.7 hole 78.7: 1(0,0)
  silkscreen extent -75,-75 75,75
SOD-323_L1.7-W1.3-LS2.5-BI [mil]
  rect 31.5x31.5 smd: 1(-47.4,0) 2(47.4,0)
  silkscreen extent -34,-27 33,28
SOD-323_L1.8-W1.3-LS2.5-RD [mil]
  rect 39.4x27.6 smd: 1(-46.2,0) 2(46.2,0)
  silkscreen extent -43,-32 36,32
SOT-23-5_L2.9-W1.6-P0.95-LS2.8-TL [mil]
  rect 43.3x23.6 smd paste+0 mask+2: 1(-51.2,37.4) 2(-51.2,0) 3(-51.2,-37.4) 4(51.2,-37.4) 5(51.2,37.4)
  silkscreen extent -32,-60 32,59
SOT-553-5_L1.6-W1.2-P0.50-LS1.6-BL#1 [mil]
  rect 11x22.8 smd paste+0 mask+0.8: 1(-19.7,-28.2) 2(0,-28.2) 3(19.7,-28.2) 4(19.7,28.3) 5(-19.7,28.3)
  silkscreen extent -41,-46 34,27
SOT-553-5_L1.6-W1.2-P0.50-LS1.6-BL#2 [mil]
  rect 11x22.8 smd paste+0 mask+0.8: 1(-19.6,-28.3) 2(0,-28.3) 3(19.7,-28.3) 4(19.7,28.2) 5(-19.6,28.2)
  silkscreen extent -41,-46 35,27
SOT-553-5_L1.6-W1.2-P0.50-LS1.6-BL#3 [mil]
  rect 11x22.8 smd paste+0 mask+0.8: 1(-19.6,-28.2) 2(0,-28.2) 3(19.7,-28.2) 4(19.7,28.3) 5(-19.6,28.3)
  silkscreen extent -41,-46 34,27
SOT-563-6_L1.6-W1.2-P0.50-LS1.6-BL#1 [mil]
  rect 11x26.8 smd: 1(-19.7,-25.2) 2(0,-25.2) 3(19.6,-25.2) 4(19.6,25.2) 5(0,25.2) 6(-19.7,25.2)
  silkscreen extent -40,-40 34,27
SOT-563-6_L1.6-W1.2-P0.50-LS1.6-BL#2 [mil]
  rect 11x26.8 smd: 1(-19.6,-25.2) 2(0,-25.2) 3(19.7,-25.2) 4(19.7,25.2) 5(0,25.2) 6(-19.6,25.2)
  silkscreen extent -40,-40 34,27
SW-SMD_L3.9-W2.9-LS4.8SWQC_SPST [mil]
  rect 70.9x39.4 smd paste+0 mask+2: 1(0,82.7) 2(0,-82.6)
  Board Outline Layer lines w0.1: -35.2,15.2 -38.7,14.8 -42.1,13.6 -45.1,11.8 -47.6,9.3 -49.4,6.3 -50.6,2.9 -51,-0.6 -50.6,-4.1 -49.4,-7.4 -47.6,-10.4 -45.1,-12.9 -42.1,-14.8 -38.7,-15.9 -35.2,-16.3 -31.7,-15.9 -28.4,-14.8 -25.4,-12.9 -22.9,-10.4 -21.1,-7.4 -19.9,-4.1 -19.5,-0.6 -19.9,2.9 -21.1,6.3 -22.9,9.3 -25.4,11.8 -28.4,13.6 -31.7,14.8 -35.2,15.2 ; 35.6,15.2 32.1,14.8 28.8,13.6 25.8,11.8 23.3,9.3 21.4,6.3 20.3,2.9 19.9,-0.6 20.3,-4.1 21.4,-7.4 23.3,-10.4 25.8,-12.9 28.8,-14.8 32.1,-15.9 35.6,-16.3 39.1,-15.9 42.5,-14.8 45.4,-12.9 47.9,-10.4 49.8,-7.4 51,-4.1 51.4,-0.6 51,2.9 49.8,6.3 47.9,9.3 45.4,11.8 42.5,13.6 39.1,14.8 35.6,15.2
  Board Outline Layer region: -19.5,-0.6 -19.9,-4.1 -21.1,-7.4 -22.9,-10.4 -25.4,-12.9 -28.4,-14.8 -31.7,-15.9 -35.2,-16.3 -38.7,-15.9 -42.1,-14.8 -45.1,-12.9 -47.6,-10.4 -49.4,-7.4 -50.6,-4.1 -51,-0.6 -50.6,2.9 -49.4,6.3 -47.6,9.3 -45.1,11.8 -42.1,13.6 -38.7,14.8 -35.2,15.2 -31.7,14.8 -28.4,13.6 -25.4,11.8 -22.9,9.3 -21.1,6.3 -19.9,2.9
  Board Outline Layer region: -19.5,-0.6 -19.9,-4.1 -21.1,-7.4 -22.9,-10.4 -25.4,-12.9 -28.4,-14.8 -31.7,-15.9 -35.2,-16.3 -38.7,-15.9 -42.1,-14.8 -45.1,-12.9 -47.6,-10.4 -49.4,-7.4 -50.6,-4.1 -51,-0.6 -50.6,2.9 -49.4,6.3 -47.6,9.3 -45.1,11.8 -42.1,13.6 -38.7,14.8 -35.2,15.2 -31.7,14.8 -28.4,13.6 -25.4,11.8 -22.9,9.3 -21.1,6.3 -19.9,2.9
  Board Outline Layer region: 51.4,-0.6 51,-4.1 49.8,-7.4 47.9,-10.4 45.4,-12.9 42.5,-14.8 39.1,-15.9 35.6,-16.3 32.1,-15.9 28.8,-14.8 25.8,-12.9 23.3,-10.4 21.4,-7.4 20.3,-4.1 19.9,-0.6 20.3,2.9 21.4,6.3 23.3,9.3 25.8,11.8 28.8,13.6 32.1,14.8 35.6,15.2 39.1,14.8 42.5,13.6 45.4,11.8 47.9,9.3 49.8,6.3 51,2.9
  Board Outline Layer region: 51.4,-0.6 51,-4.1 49.8,-7.4 47.9,-10.4 45.4,-12.9 42.5,-14.8 39.1,-15.9 35.6,-16.3 32.1,-15.9 28.8,-14.8 25.8,-12.9 23.3,-10.4 21.4,-7.4 20.3,-4.1 19.9,-0.6 20.3,2.9 21.4,6.3 23.3,9.3 25.8,11.8 28.8,13.6 32.1,14.8 35.6,15.2 39.1,14.8 42.5,13.6 45.4,11.8 47.9,9.3 49.8,6.3 51,2.9
  Multi-Layer board cut-out: -19.5,-0.6 -19.9,-4.1 -21.1,-7.4 -22.9,-10.4 -25.4,-12.9 -28.4,-14.8 -31.7,-15.9 -35.2,-16.3 -38.7,-15.9 -42.1,-14.8 -45.1,-12.9 -47.6,-10.4 -49.4,-7.4 -50.6,-4.1 -51,-0.6 -50.6,2.9 -49.4,6.3 -47.6,9.3 -45.1,11.8 -42.1,13.6 -38.7,14.8 -35.2,15.2 -31.7,14.8 -28.4,13.6 -25.4,11.8 -22.9,9.3 -21.1,6.3 -19.9,2.9
  Multi-Layer board cut-out: 51.4,-0.6 51,-4.1 49.8,-7.4 47.9,-10.4 45.4,-12.9 42.5,-14.8 39.1,-15.9 35.6,-16.3 32.1,-15.9 28.8,-14.8 25.8,-12.9 23.3,-10.4 21.4,-7.4 20.3,-4.1 19.9,-0.6 20.3,2.9 21.4,6.3 23.3,9.3 25.8,11.8 28.8,13.6 32.1,14.8 35.6,15.2 39.1,14.8 42.5,13.6 45.4,11.8 47.9,9.3 49.8,6.3 51,2.9
  silkscreen extent -57,-77 83,77
TDFN-8_L3.0-W2.0-P0.50-TL-EP#1 [mil]
  rect 23x11 smd: 1(-55.8,29.6) 2(-55.8,9.9) 3(-55.8,-9.8) 4(-55.8,-29.5) 5(55.8,-29.5) 6(55.8,-9.8) 7(55.8,9.9) 8(55.8,29.6)
  rect 59.1x61 smd: 9(0,0)
  silkscreen extent -82,-42 62,42
TDFN-8_L3.0-W2.0-P0.50-TL-EP#2 [mil]
  rect 23x11 smd: 1(-55.8,29.5) 2(-55.8,9.8) 3(-55.8,-9.9) 4(-55.8,-29.6) 5(55.8,-29.6) 6(55.8,-9.9) 7(55.8,9.8) 8(55.8,29.5)
  rect 59.1x61 smd: 9(0,0)
  silkscreen extent -82,-42 62,42
USB-SMD_USB4081-03-A#1 [mil]
  oval 43.3x82.7 hole 23.6 slot 63 at 90 deg paste+0 mask+2: 1(-170.1,68.7) 2(170.1,68.7) 3(170.1,-88.8) 4(-170.1,-88.8)
  rect 17.7x27.6 smd paste-3937 mask+2: 5(-129.9,33.7) 6(129.9,33.7)
  rect 11.8x27.6 smd paste-3937 mask+2: A1(-118.1,88.8) A2(-98.4,88.8) A3(-78.7,88.8) A4(-59,88.8) A5(-39.3,88.8) A6(-19.6,88.8) A7(19.8,88.8) A8(39.4,88.8) A9(59.1,88.8) A10(78.8,88.8) A11(98.5,88.8) A12(118.2,88.8)
  rect 9.8x27.6 smd paste-3937 mask+2: B1(108.3,33.7) B2(88.6,33.7) B3(68.9,33.7) B4(49.2,33.7) B5(29.5,33.7) B6(9.8,33.7) B7(-9.8,33.7) B8(-29.5,33.7) B9(-49.2,33.7) B10(-68.9,33.7) B11(-88.6,33.7) B12(-108.3,33.7)
  Board Outline Layer lines w10: -177.2,-163.5 175.2,-163.5
  silkscreen extent -177,-215 175,90
USB-SMD_USB4081-03-A#2 [mil]
  oval 43.3x82.7 hole 23.6 slot 63 at 90 deg paste+0 mask+2: 1(-170.1,68.7) 2(170.1,68.7) 3(170.1,-88.8) 4(-170.1,-88.8)
  rect 17.7x27.6 smd paste-3937 mask+2: 5(-129.9,33.6) 6(129.9,33.6)
  rect 11.8x27.6 smd paste-3937 mask+2: A1(-118.1,88.7) A2(-98.4,88.7) A3(-78.7,88.7) A4(-59,88.7) A5(-39.3,88.7) A6(-19.6,88.7) A7(19.8,88.7) A8(39.4,88.7) A9(59.1,88.7) A10(78.8,88.7) A11(98.5,88.7) A12(118.2,88.7)
  rect 9.8x27.6 smd paste-3937 mask+2: B1(108.3,33.6) B2(88.6,33.6) B3(68.9,33.6) B4(49.2,33.6) B5(29.5,33.6) B6(9.8,33.6) B7(-9.8,33.6) B8(-29.5,33.6) B9(-49.2,33.6) B10(-68.9,33.6) B11(-88.6,33.6) B12(-108.3,33.6)
  Board Outline Layer lines w10: 175.2,-163.6 -177.2,-163.6
  silkscreen extent -177,-215 175,90
USB-SMD_USB4081-03-A#3 [mil]
  oval 43.3x82.7 hole 23.6 slot 63 at 90 deg paste+0 mask+2: 1(-170.1,68.7) 2(170.1,68.7) 3(170.1,-88.8) 4(-170.1,-88.8)
  rect 17.7x27.6 smd paste-3937 mask+2: 5(-129.9,33.6) 6(129.9,33.6)
  rect 11.8x27.6 smd paste-3937 mask+2: A1(-118.1,88.7) A2(-98.4,88.7) A3(-78.7,88.7) A4(-59,88.7) A5(-39.3,88.7) A6(-19.6,88.7) A7(19.8,88.7) A8(39.4,88.7) A9(59.1,88.7) A10(78.8,88.7) A11(98.5,88.7) A12(118.2,88.7)
  rect 9.8x27.6 smd paste-3937 mask+2: B1(108.3,33.6) B2(88.6,33.6) B3(68.9,33.6) B4(49.2,33.6) B5(29.5,33.6) B6(9.9,33.6) B7(-9.8,33.6) B8(-29.5,33.6) B9(-49.2,33.6) B10(-68.9,33.6) B11(-88.6,33.6) B12(-108.3,33.6)
  Board Outline Layer lines w10: 175.2,-163.6 -177.2,-163.6
  silkscreen extent -177,-215 175,90
WQFN-20_L4.0-W3.0-P0.50-BL-EP#1 [mil]
  oval 11.8x35.4 smd paste-3937 mask+2: 1(-49.2,-59.1) 2(-29.5,-59.1) 3(-9.8,-59.1) 4(9.8,-59.1) 5(29.5,-59.1) 6(49.2,-59.1) 11(49.2,59) 12(29.5,59) 13(9.8,59) 14(-9.8,59) 15(-29.5,59) 16(-49.2,59)
  oval 35.4x11.8 smd paste-3937 mask+2: 7(78.7,-29.6) 8(78.7,-9.9) 9(78.7,9.8) 10(78.7,29.5) 17(-78.7,29.5) 18(-78.7,9.8) 19(-78.7,-9.9) 20(-78.7,-29.6)
  rect 102.4x63 smd paste-3937 mask+2: 21(0,-0.1)
  silkscreen extent -90,-90 90,70
WQFN-20_L4.0-W3.0-P0.50-BL-EP#2 [mil]
  oval 11.8x35.4 smd paste-3937 mask+2: 1(-49.2,-59) 2(-29.5,-59) 3(-9.8,-59) 4(9.9,-59) 5(29.6,-59) 6(49.2,-59) 11(49.2,59.1) 12(29.6,59.1) 13(9.9,59.1) 14(-9.8,59.1) 15(-29.5,59.1) 16(-49.2,59.1)
  oval 35.4x11.8 smd paste-3937 mask+2: 7(78.8,-29.5) 8(78.8,-9.8) 9(78.8,9.9) 10(78.8,29.6) 17(-78.7,29.6) 18(-78.7,9.9) 19(-78.7,-9.8) 20(-78.7,-29.5)
  rect 102.4x63 smd paste-3937 mask+2: 21(0,0)
  silkscreen extent -90,-90 90,70
WQFN-20_L4.0-W3.0-P0.50-BL-EP#3 [mil]
  oval 11.8x35.4 smd paste-3937 mask+2: 1(-49.2,-59) 2(-29.5,-59) 3(-9.8,-59) 4(9.9,-59) 5(29.5,-59) 6(49.2,-59) 11(49.2,59.1) 12(29.5,59.1) 13(9.9,59.1) 14(-9.8,59.1) 15(-29.5,59.1) 16(-49.2,59.1)
  oval 35.4x11.8 smd paste-3937 mask+2: 7(78.8,-29.5) 8(78.8,-9.8) 9(78.8,9.9) 10(78.8,29.5) 17(-78.7,29.5) 18(-78.7,9.9) 19(-78.7,-9.8) 20(-78.7,-29.5)
  rect 102.4x63 smd paste-3937 mask+2: 21(0,0)
  silkscreen extent -90,-90 90,70
WQFN-20_L4.0-W3.0-P0.50-BL-EP#4 [mil]
  oval 11.8x35.4 smd paste-3937 mask+2: 1(-49.2,-59.1) 2(-29.5,-59.1) 3(-9.8,-59.1) 4(9.9,-59.1) 5(29.5,-59.1) 6(49.2,-59.1) 11(49.2,59) 12(29.5,59) 13(9.9,59) 14(-9.8,59) 15(-29.5,59) 16(-49.2,59)
  oval 35.4x11.8 smd paste-3937 mask+2: 7(78.8,-29.6) 8(78.8,-9.9) 9(78.8,9.8) 10(78.8,29.5) 17(-78.7,29.5) 18(-78.7,9.8) 19(-78.7,-9.9) 20(-78.7,-29.6)
  rect 102.4x63 smd paste-3937 mask+2: 21(0,0)
  silkscreen extent -90,-90 90,70

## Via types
v1: diameter 24, hole 12, Top Layer to Bottom Layer, 96 vias

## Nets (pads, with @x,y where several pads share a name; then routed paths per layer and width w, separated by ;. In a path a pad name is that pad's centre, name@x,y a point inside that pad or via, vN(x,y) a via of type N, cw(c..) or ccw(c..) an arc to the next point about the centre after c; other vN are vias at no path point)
$1N1259: D1.2 Q1.3 R5.1 | length 124.2
  Top Layer w10: R5.1@3731.5,5301.8 3769.8,5301.8 D1.2@3785.3,5317.3 3791.2,5323.1 Q1.3@3791.2,5378.8
$1N1313: D2.1 J1.3 Q1.1 Q1.2 Q1.5 Q1.6 Q1.7 | length 522
  Top Layer w10: Q1.1@3791.2,5429.9 Q1.2@3791.2,5404.3 Q1.5@3870,5404.3 3870,5412.7 ; D2.1@3878.9,5242.3 3878.9,5269.5 3908.3,5298.9 3908.3,5372.7 3878.9,5402 3878.9,5403.7 3870,5412.7 ; J1.3@4047.6,5468.5 4009,5429.9 Q1.6@3870,5429.9 3870,5412.7
$1N13203: LED5.1 R36.1 | length 150.5
  Top Layer w10: R36.1@3117.6,4015 3117.6,4028 3094.5,4051.1 3094.5,4087.7 3100.9,4094.2 3128.5,4094.2 3140.9,4106.6 LED5.1@3140.9,4120.6
$1N13246: Q2.5 R33.1 | length 52.2
  Top Layer w10: R33.1@3177.6,4015 3179.7,4017.1 3179.7,4025.9 3191.2,4037.5 Q2.5@3191.2,4061.6
$1N13260: Q2.4 R34.1 | length 54.2
  Top Layer w10: R34.1@3177.6,4185 3179.7,4182.9 3179.7,4174.1 3191.2,4162.5 Q2.4@3191.2,4136.4
$1N13283: R79.1 U11.17 | length 49
  Top Layer w10: U11.17@3823.6,3708.7 3825.8,3706.5 R79.1@3825.8,3660.6
$1N13322: LED13.1 R81.1 | length 81.7
  Top Layer w10: LED13.1@3981.3,3723 3989.3,3731 R81.1@3989.3,3801.4
$1N13324: LED5.2 R35.1 | length 66.2
  Top Layer w10: LED5.2@3113.3,4120.6 3117.6,4124.9 R35.1@3117.6,4185
$1N16078: R16.2 R17.1 U7.3
$1N16234: LED1.2 R18.2
$1N24572: R105.1 R110.1 U22.8 | length 1406.8
  Bottom Layer w10: R105.1@4082.6,5027.6 4056.7,5053.6 3916.2,5053.6 3734.8,5235 3574.8,5235 3522.2,5287.6 U22.8@3522.2,5338 3522.2,5355.6 3615.2,5448.6 3875.4,5448.6 3944.1,5380 4007.2,5380 4082.6,5455.5 R110.1@4082.6,5467.6
$1N24631: R106.1 R111.1 U22.1 | length 343.1
  Bottom Layer w10: U22.1@3825.3,5338 3868.3,5295 4015.3,5295 R111.1@4082.6,5227.6 R106.1@4082.6,5187.6
$1N24642: R107.1 R112.1 U22.2 | length 821.4
  Bottom Layer w10: R107.1@4082.6,5147.6 4050,5115 3934.4,5115 3782,5267.4 U22.2@3782,5322.2 3798.6,5338.8 3798.6,5372.1 3805,5378.5 3845.6,5378.5 3915.2,5309 4041.2,5309 R112.1@4082.6,5267.6
$1N24649: R114.1 U22.5 | length 529
  Bottom Layer w10: U22.5@3652.1,5338 3668.7,5354.6 3668.7,5379.9 3709.3,5420.6 3863.8,5420.6 3933.3,5351.1 4055.6,5351.1 4082.6,5378.1 R114.1@4082.6,5387.6
$1N24659: R104.1 R109.1 U22.7 | length 1268.5
  Bottom Layer w10: R104.1@4082.6,5067.6 3922,5067.6 3740.6,5249 3644.9,5249 3582.1,5311.8 3582.1,5321.5 U22.7@3565.5,5338 3582.1,5354.6 3582.1,5380 3636.6,5434.6 3869.6,5434.6 3939.2,5365.1 4032.2,5365.1 4082.6,5415.5 R109.1@4082.6,5427.6
$1N24671: R108.1 R113.1 U22.3 | length 876
  Bottom Layer w10: R108.1@4082.6,5107.6 4075,5100 3929.6,5100 3738.7,5290.9 U22.3@3738.7,5338 3755.3,5354.6 3755.3,5356.3 3761.7,5362.8 3769.5,5362.8 3799.2,5392.6 3852.2,5392.6 3921.7,5323 4067.2,5323 R113.1@4082.6,5307.6
$1N24731: C5.2 L1.1 U1.2 | length 148.5
  Top Layer w10: L1.1@3839.1,5057.3 3839.1,5105.9 3842.3,5109.2 3842.3,5127.6 3848.8,5134.1 3863.5,5134.1 U1.2@3866.7,5137.3 3869.9,5134.1 3884.6,5134.1 3894.5,5124.2 C5.2@3909.8,5124.2
$1N24732: C5.1 U1.4 | length 113.2
  Top Layer w10: U1.4@3816.3,5156.9 3832.8,5173.4 3884.6,5173.4 3891.1,5167 3891.1,5164.5 C5.1@3909.8,5145.8
$1N24733: C4.1 R1.1 R2.1 U1.6 | length 150.9
  Top Layer w10: C4.1@3716.5,5083.1 R2.1@3716.5,5127.8 3718.6,5129.8 3727.4,5129.8 3728.1,5130.5 R1.1@3759.8,5130.5 3772.7,5117.6 U1.6@3816.3,5117.6
$1N24736: R3.1 R4.2 U1.5 | length 165.9
  Top Layer w10: R4.2@3691.5,5216.8 3729.5,5216.8 R3.1@3731.5,5218.7 3791.9,5158.3 3791.9,5146.9 3798.4,5140.5 3809.8,5140.5 3813,5137.3 U1.5@3816.3,5137.3
$1N24745: C11.2 L2.1 U2.2 | length 219.3
  Top Layer w10: L2.1@3534.8,5282.6 3558.4,5282.6 3574.5,5298.6 3574.5,5302.2 3597.2,5324.9 3604.5,5324.9 3610.9,5331.3 3610.9,5335 3612.6,5336.7 3612.6,5351.4 ; C11.2@3620.6,5420 3620.6,5398.8 3612.6,5390.8 3612.6,5351.4 ; U2.2@3636.9,5361 3633.7,5357.9 3619,5357.9 3612.6,5351.4
$1N24746: C11.1 U2.4 | length 44.5
  Top Layer w10: U2.4@3586.5,5380.7 3598.5,5392.7 3598.5,5396.6 3599,5397 C11.1@3599,5420
$1N24747: C10.1 R6.1 R7.1 R8.1 R9.2 U2.6 | length 347.6
  Top Layer w10: U2.6@3586.5,5341.4 3583.2,5338.1 3565.2,5338.1 3555.7,5328.5 3533.8,5328.5 3527.4,5335 3527.4,5377.6 3586.5,5436.7 3586.5,5446.3 R9.2@3600.3,5460 ; C10.1@3589.6,5230.4 3628.4,5230.4 R8.1@3629.6,5229.1 3631.9,5231.3 R6.1@3631.9,5272.7 R7.1@3591.9,5272.7
$1N24748: R10.1 U2.5 | length 43.2
  Top Layer w10: R10.1@3544.8,5364.5 3546.8,5362.4 3555.7,5362.4 3557.1,5361 U2.5@3586.5,5361
$1N24760: L3.2 U3.6 | length 81.1
  Bottom Layer w10: U3.6@3906.8,3496 3906.8,3420.1 L3.2@3910.5,3416.4
$1N24761: L3.1 U3.7 | length 83
  Bottom Layer w10: L3.1@3879,3416.4 3887.1,3424.5 U3.7@3887.1,3496
$1N24762: L4.1 U4.7 | length 83.6
  Bottom Layer w10: L4.1@3779,3416.4 3788.7,3426.1 U4.7@3788.7,3496
$1N24763: L4.2 U4.6 | length 80.5
  Bottom Layer w10: U4.6@3808.4,3496 3810.5,3493.9 L4.2@3810.5,3416.4
$1N24773: L5.1 U5.7 | length 82.3
  Bottom Layer w10: L5.1@3679,3416.4 3689.9,3427.3 U5.7@3689.9,3494.2
$1N24774: L5.2 U5.6 | length 78.2
  Bottom Layer w10: U5.6@3709.6,3494.2 3710.5,3493.3 L5.2@3710.5,3416.4
$1N24784: L6.1 U6.7 | length 84.1
  Bottom Layer w10: L6.1@3579,3416.4 3589.9,3427.3 U6.7@3589.9,3496
$1N24785: L6.2 U6.6 | length 80
  Bottom Layer w10: U6.6@3609.6,3496 3610.5,3495.1 L6.2@3610.5,3416.4
$1N24845: R15.2 U7.1
$1N24848: R18.1 U7.4
$1N24879: R22.1 U8.4
$1N24882: R19.2 U8.1
$1N24886: LED2.2 R22.2
$1N24888: R20.2 R21.1 U8.3
$1N24889: R26.1 U9.4
$1N24890: R30.1 U10.4
$1N24895: R23.2 U9.1
$1N24896: R27.2 U10.1
$1N24903: LED4.2 R30.2
$1N24904: LED3.2 R26.2
$1N24907: R28.2 R29.1 U10.3
$1N24908: R24.2 R25.1 U9.3
$1N24946: LED6.2 R38.1 | length 61.2
  Top Layer w10: LED6.2@3113.3,4345.6 3117.6,4349.9 R38.1@3117.6,4405
$1N24947: Q3.4 R41.1 | length 53.1
  Top Layer w10: R41.1@3177.6,4405 3177.6,4370.7 Q3.4@3190.9,4357.4
$1N24948: Q3.5 R40.1 | length 53.1
  Top Layer w10: R40.1@3177.6,4235 3177.6,4269.3 Q3.5@3190.9,4282.6
$1N24949: LED6.1 R39.1 | length 153
  Top Layer w10: R39.1@3117.6,4235 3117.6,4253 3094.5,4276.1 3094.5,4312.7 3100.9,4319.2 3115.9,4319.2 3117.6,4320.8 3125.8,4320.8 3132.2,4327.3 3132.2,4336.9 LED6.1@3140.9,4345.6
$1N24959: LED7.2 R43.1 | length 61.2
  Top Layer w10: LED7.2@3113.3,4565.6 3117.6,4569.9 R43.1@3117.6,4625
$1N24960: Q4.4 R46.1 | length 53.1
  Top Layer w10: R46.1@3177.6,4625 3177.6,4590.7 Q4.4@3190.9,4577.4
$1N24961: Q4.5 R45.1 | length 53.1
  Top Layer w10: R45.1@3177.6,4455 3177.6,4489.3 Q4.5@3190.9,4502.6
$1N24962: LED7.1 R44.1 | length 152.9
  Top Layer w10: R44.1@3117.6,4455 3117.6,4473 3094.5,4496.1 3094.5,4532.7 3100.9,4539.2 3124.1,4539.2 3132.2,4547.3 3132.2,4556.9 LED7.1@3140.9,4565.6
$1N24972: LED8.2 R49.1 | length 66.2
  Top Layer w10: LED8.2@3113.3,4795.6 3113.3,4855.7 R49.1@3117.6,4860
$1N24973: Q5.4 R52.1 | length 58.1
  Top Layer w10: R52.1@3177.6,4860 3177.6,4820.7 Q5.4@3190.9,4807.4
$1N24974: Q5.5 R51.1 | length 53.1
  Top Layer w10: R51.1@3177.6,4685 3177.6,4719.3 Q5.5@3190.9,4732.6
$1N24975: LED8.1 R50.1 | length 153.9
  Top Layer w10: R50.1@3117.6,4685 3117.6,4703 3094.5,4726.1 3094.5,4762.7 3102.6,4770.8 3125.8,4770.8 3142.1,4787.2 3142.1,4794.4 LED8.1@3140.9,4795.6
$1N25006: LED12.2 R73.1 | length 66.2
  Top Layer w10: R73.1@4370.1,3995 4374.4,3999.3 LED12.2@4374.4,4059.4
$1N25007: LED11.2 R67.1 | length 60.5
  Top Layer w10: R67.1@4367,4252 4374.4,4259.3 LED11.2@4374.4,4309.4
$1N25008: LED10.2 R61.1
$1N25009: LED9.2 R55.1 | length 61.2
  Top Layer w10: R55.1@4370.1,4725 4374.4,4729.3 LED9.2@4374.4,4784.4
$1N25010: Q7.4 R64.1 | length 53.1
  Top Layer w10: Q7.4@4296.8,4537.6 4296.8,4512.2 4308.1,4500.9 4308.1,4492.1 R64.1@4310.1,4490
$1N25011: Q9.4 R76.1 | length 53.1
  Top Layer w10: Q9.4@4296.8,4042.6 4296.8,4017.2 4308.1,4005.9 4308.1,3997.1 R76.1@4310.1,3995
$1N25012: Q8.4 R70.1 | length 53.1
  Top Layer w10: Q8.4@4296.8,4297.6 4296.8,4272.2 4308.1,4260.9 4308.1,4252.1 R70.1@4310.1,4250
$1N25013: Q6.4 R58.1 | length 53.5
  Top Layer w10: Q6.4@4296.8,4772.6 4296.8,4748.2 4309,4735.9 4309,4727.1 R58.1@4311.1,4725
$1N25014: Q7.5 R63.1 | length 53.1
  Top Layer w10: Q7.5@4296.8,4612.4 4296.8,4637.8 4308.1,4649.1 4308.1,4657.9 R63.1@4310.1,4660
$1N25015: Q9.5 R75.1 | length 53.1
  Top Layer w10: Q9.5@4296.8,4117.4 4296.8,4142.8 4308.1,4154.1 4308.1,4162.9 R75.1@4310.1,4165
$1N25016: Q8.5 R69.1 | length 53.1
  Top Layer w10: Q8.5@4296.8,4372.4 4296.8,4397.8 4308.1,4409.1 4308.1,4417.9 R69.1@4310.1,4420
$1N25017: Q6.5 R57.1 | length 53.1
  Top Layer w10: Q6.5@4296.8,4847.4 4296.8,4872.8 4308.1,4884.1 4308.1,4892.9 R57.1@4310.1,4895
$1N25018: LED10.1 R62.1 | length 158.1
  Top Layer w10: LED10.1@4346.8,4544.4 4355.5,4553.1 4355.5,4562.7 4363.6,4570.8 4386.8,4570.8 4393.3,4577.3 4393.3,4613.9 4370.1,4637 R62.1@4370.1,4660
$1N25019: LED12.1 R74.1 | length 148.1
  Top Layer w10: LED12.1@4346.8,4059.4 4355.5,4068.1 4355.5,4077.7 4362,4084.2 4370.1,4084.2 4371.8,4085.8 4386.8,4085.8 4393.3,4092.3 4393.3,4128.9 4370.1,4152 R74.1@4370.1,4165
$1N25020: LED11.1 R68.1 | length 153.1
  Top Layer w10: LED11.1@4346.8,4309.4 4355.5,4318.1 4355.5,4327.7 4362,4334.2 4370.1,4334.2 4371.8,4335.8 4386.8,4335.8 4393.3,4342.3 4393.3,4378.9 4370.1,4402 R68.1@4370.1,4420
$1N25021: LED9.1 R56.1 | length 179.6
  Top Layer w10: LED9.1@4346.8,4784.4 4351.1,4788.7 4351.1,4802.7 4359.3,4810.8 4386.8,4810.8 4393.3,4817.3 4393.3,4853.9 4386.8,4860.4 4359.3,4860.4 4351.1,4868.5 R56.1@4351.1,4895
